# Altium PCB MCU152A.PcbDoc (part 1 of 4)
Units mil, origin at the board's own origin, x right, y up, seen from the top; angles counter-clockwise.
Board outline 2307.9 x 3007.9 mil, 4 copper layers (Top Signal, GND, PWR, Bottom Signal), stack 61.6 mil thick; 198 components, 136 nets, 740 pads, 401 vias.
Unrouted connection lines stored in the file: 147.
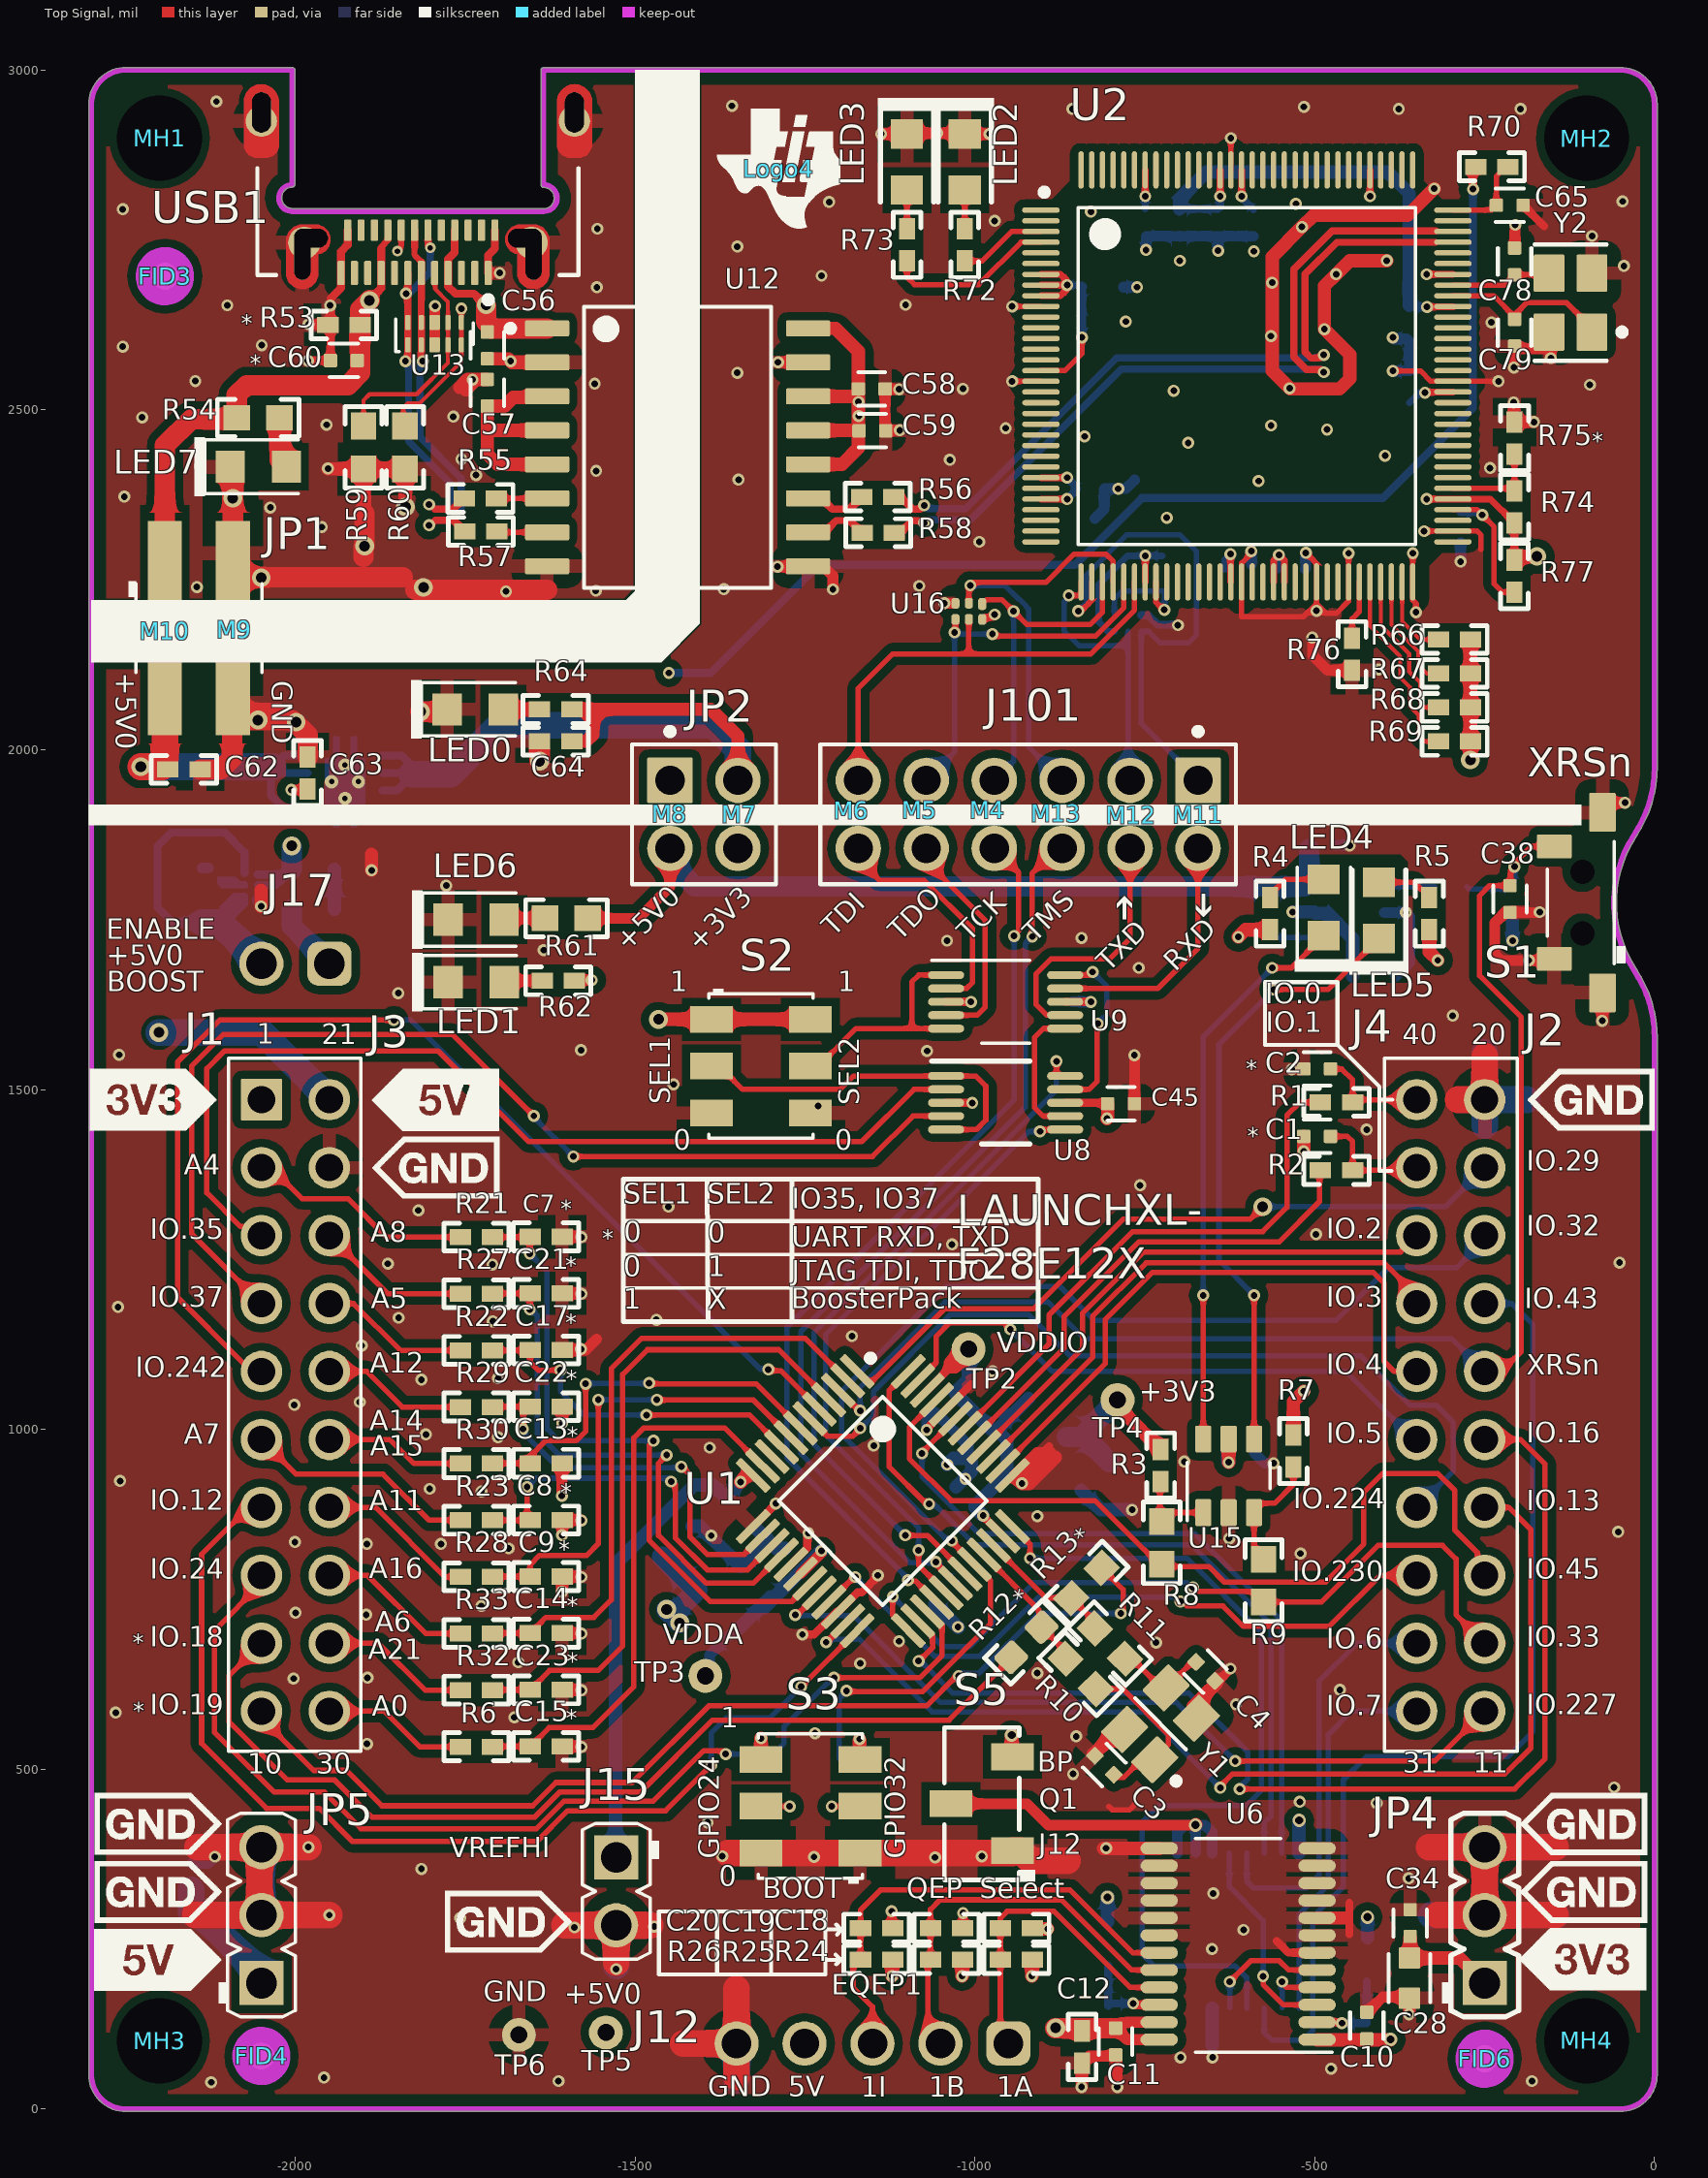
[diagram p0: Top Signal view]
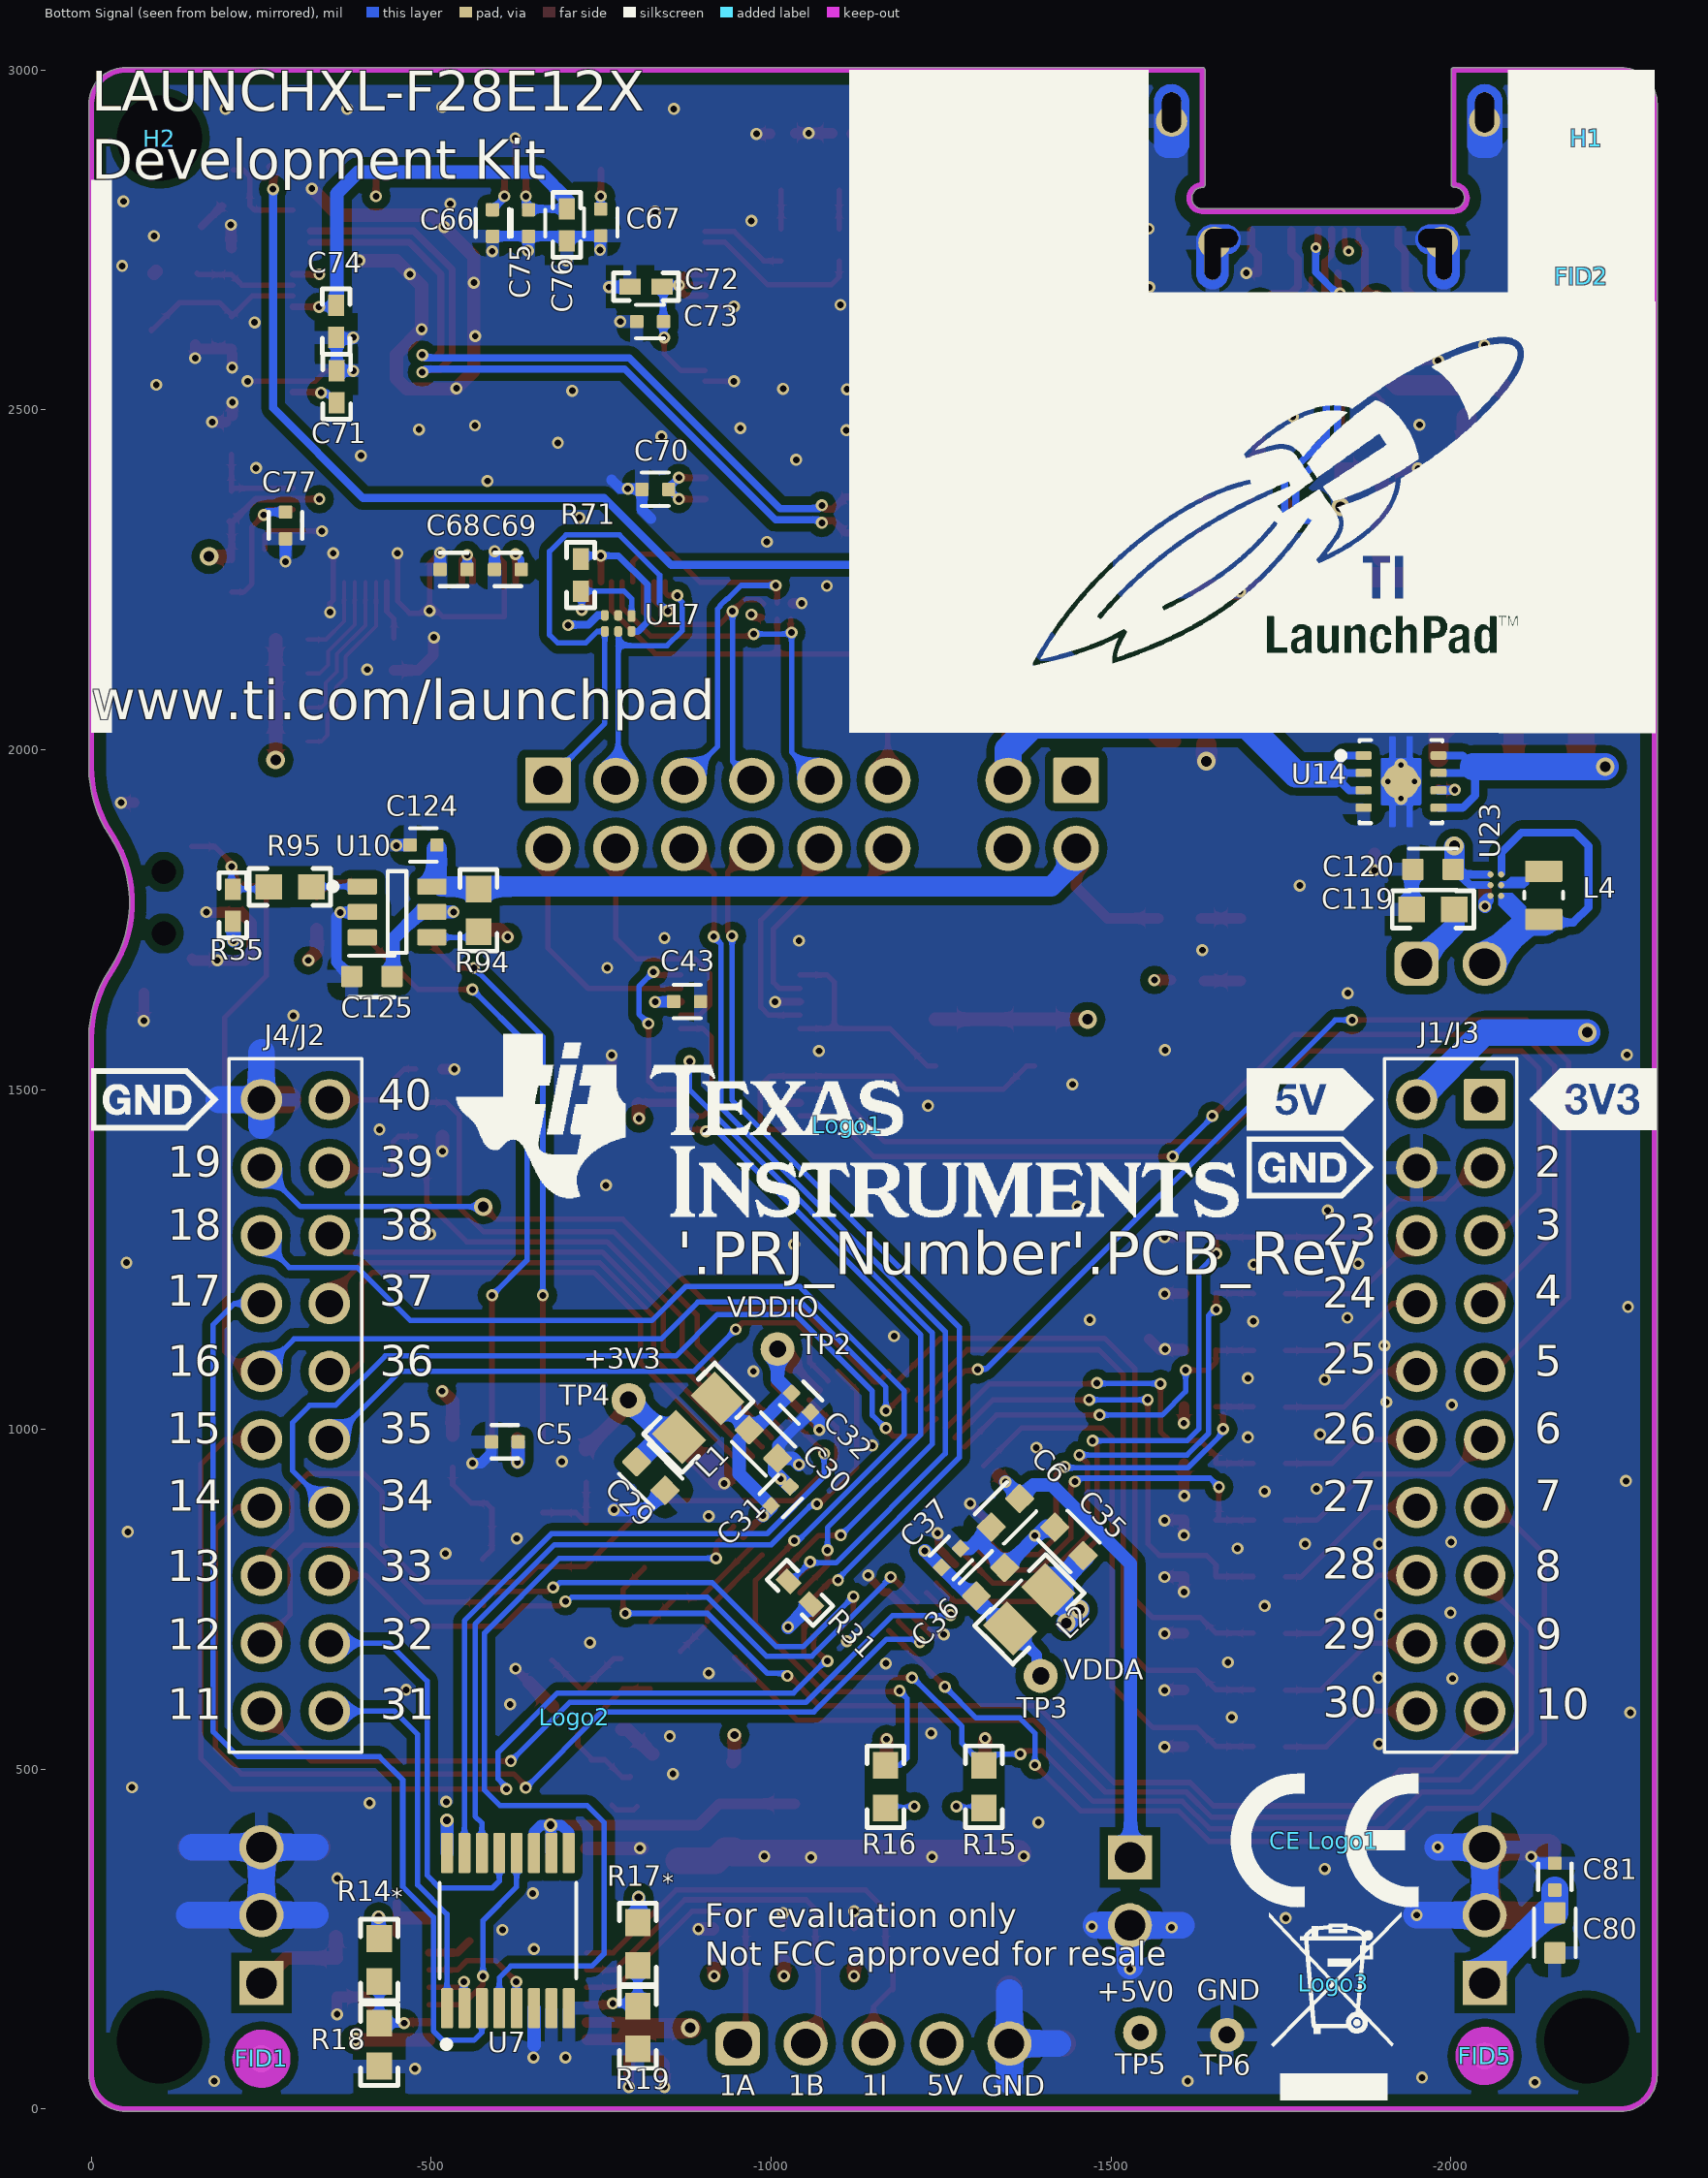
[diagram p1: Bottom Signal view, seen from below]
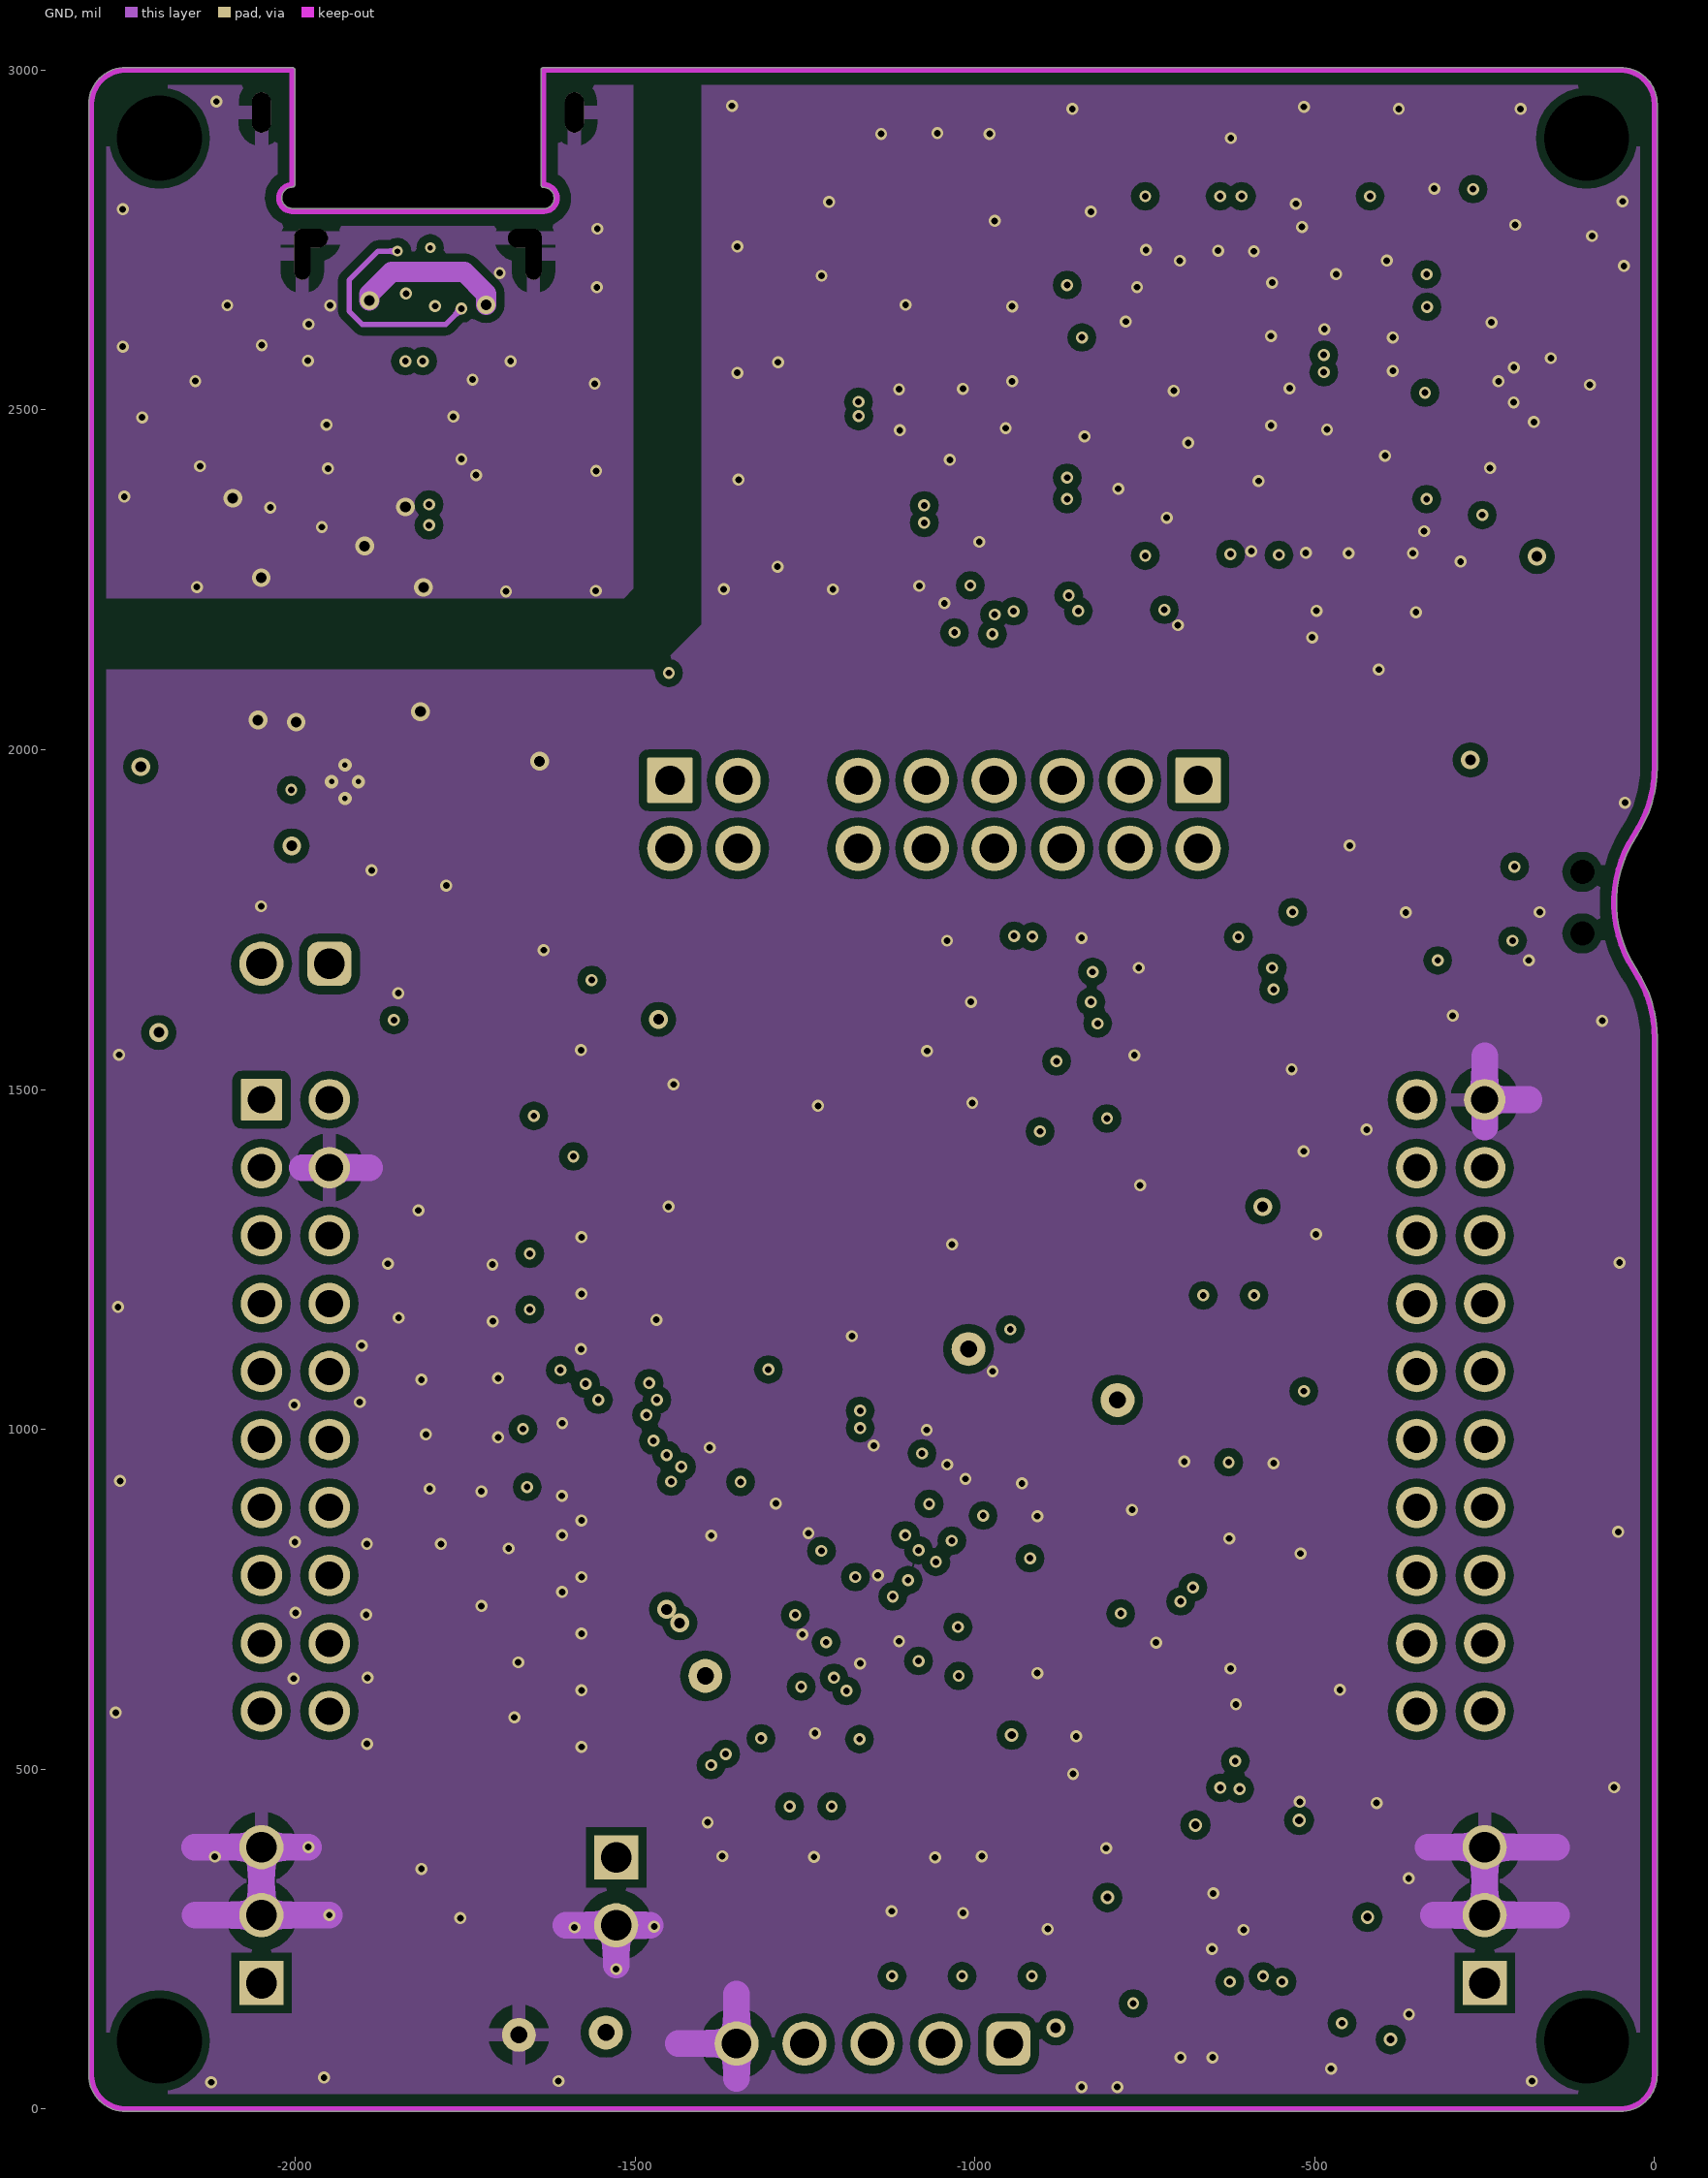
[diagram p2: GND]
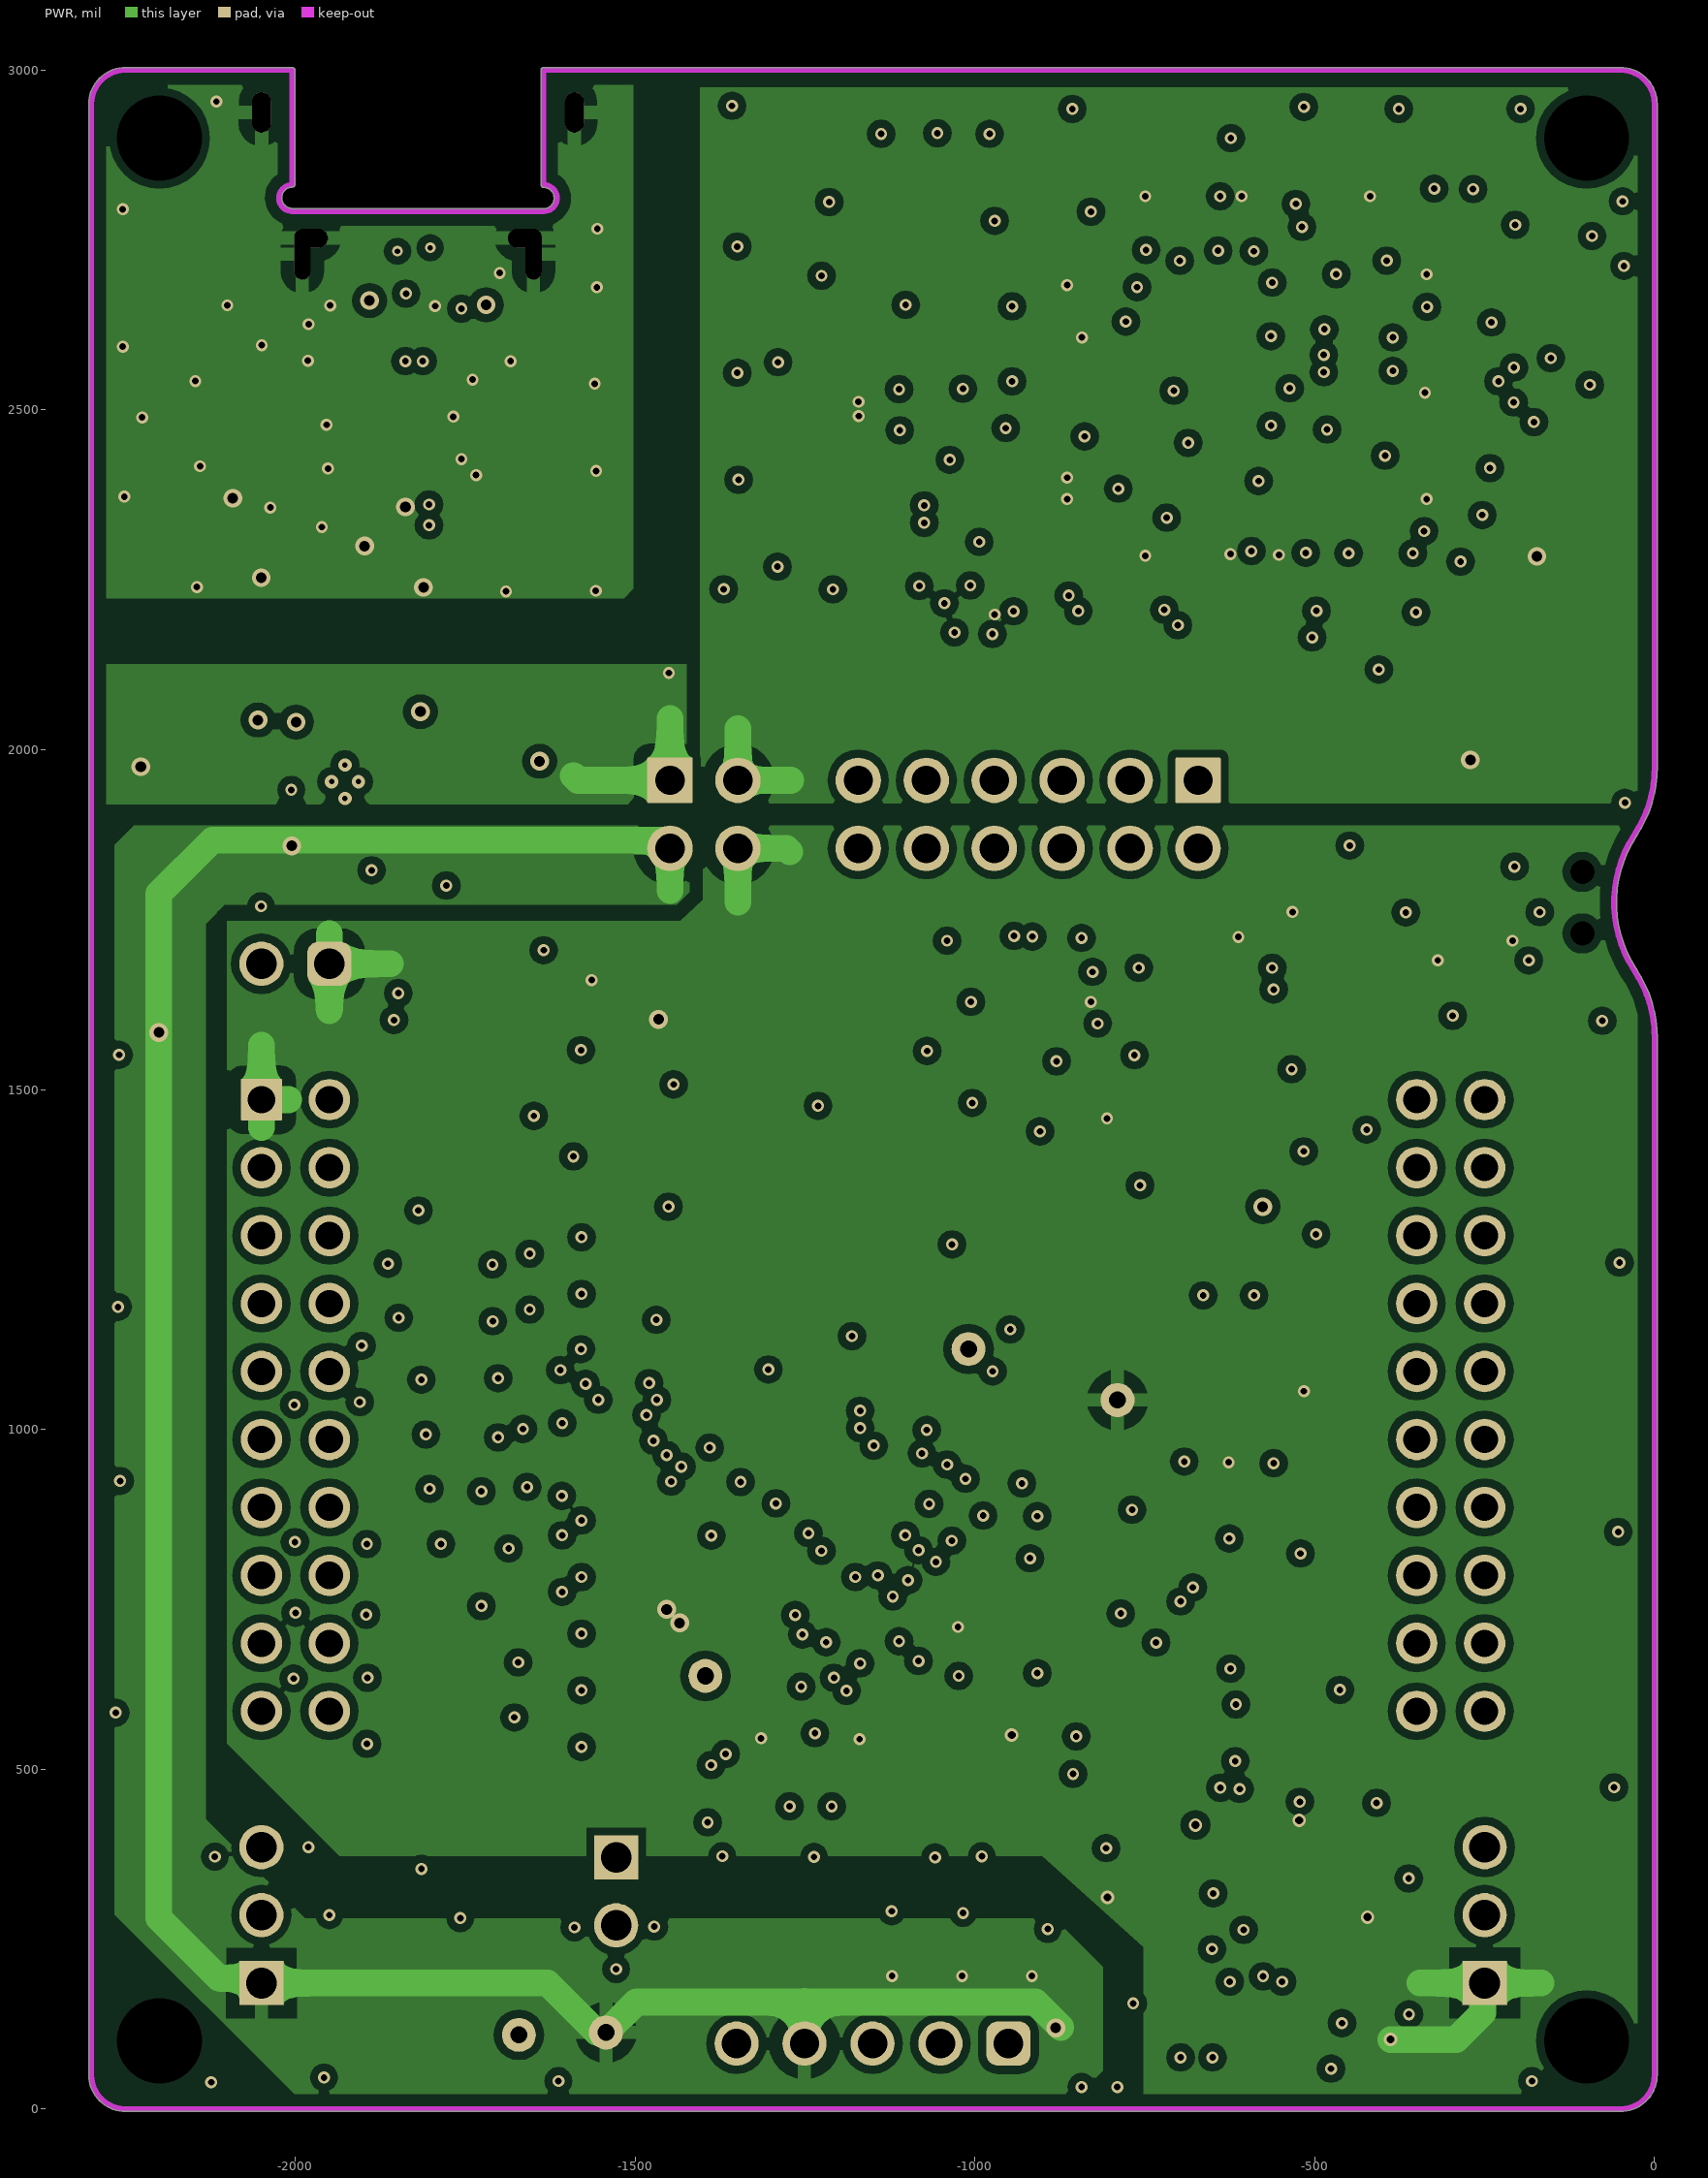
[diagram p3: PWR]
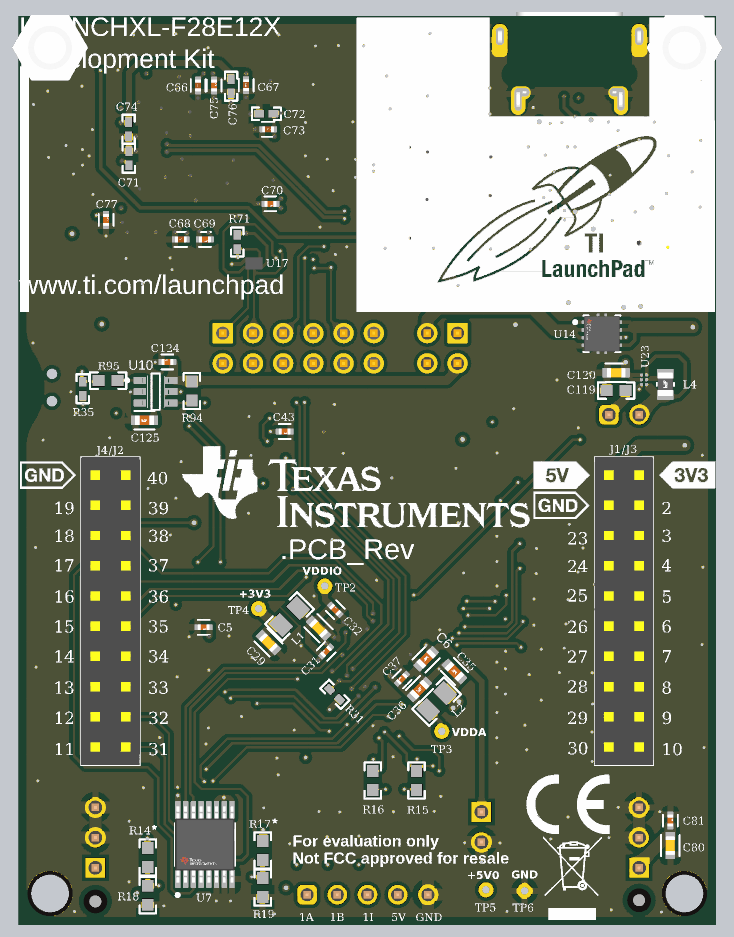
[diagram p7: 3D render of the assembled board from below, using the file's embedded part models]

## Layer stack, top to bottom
Top Solder: solder mask 0.4, Solder Resist, Dk 3.5
Top Signal: signal copper 1.4
Dielectric 1: prepreg 8, FR-4, Dk 4.2
GND: signal copper 1.4
Dielectric 2: core 40, FR-4, Dk 4.2
PWR: signal copper 1.4
Dielectric 3: prepreg 8, FR-4, Dk 4.2
Bottom Signal: signal copper 1.4
Bottom Solder: solder mask 0.4, Solder Resist, Dk 3.5

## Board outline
-2303.95,49.97 cw(c-2300,50) -2303.95,50 -2303.95,2950 cw(c-2250,2950) -2250,3003.95 -2004.72,3003.95 cw(c-2004.72,3000) -2000.77,3000 -2000.77,2832 cw(c-2004.72,2832) -2004.65,2828.05 ccw(c-2004.37,2812.32) -2005.38,2796.62 cw(c-2005.64,2792.67) -2003.63,2796.08 -1634.65,2796.08 cw(c-1634.65,2792.13) -1634.38,2796.07 cw(c-1633.73,2792.17) -1633.99,2796.12 ccw(c-1635,2811.82) -1619.27,2811.82 ccw(c-1635,2811.82) -1634.72,2827.55 cw(c-1634.65,2831.5) -1638.6,2831.5 -1638.6,3000 cw(c-1634.65,3000) -1634.62,3003.95 -50,3003.95 cw(c-50,2950) 3.95,2950 3.95,1975 cw(c-181.67,1975) -26.7,1872.82 ccw(c121.67,1775) -26.7,1677.18 cw(c-181.67,1575) 3.95,1575 3.95,50.03 cw(c0,50) 3.95,50 cw(c-50,50) -50,-3.95 -2250,-3.95 cw(c-2250,50)

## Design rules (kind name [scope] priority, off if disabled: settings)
AcuteAngle [All] p1: minimum=4.50000000000000E+0001 checktracksonly=FALSE
AssemblyTestPointUsage [All] p1: valid=2
BoardOutlineClearance BoardOutlineClearance_MountingHoles [OnCopper and InComponentClass('Mounting Holes')] p1: gap=40 ignorepadtopadclearanceinfootprint=FALSE
BoardOutlineClearance BoardOutlineClearance_Poly [OnCopper and IsPoly] p2: gap=25 ignorepadtopadclearanceinfootprint=FALSE
BoardOutlineClearance BoardOutlineClearance_USB101 [InComponent('USB1')] p3: gap=0 ignorepadtopadclearanceinfootprint=FALSE
BoardOutlineClearance [OnCopper and Not InComponentClass('Logo') and not InComponentClass('FiducialMark') and not InRegion(1000,500,4000,800) and not InPoly] p4: gap=10 ignorepadtopadclearanceinfootprint=FALSE
Clearance USB101 [InComponent('USB1') vs OnLayer('Keep-Out Layer')] p1: gap=7.87 ignorepadtopadclearanceinfootprint=FALSE
Clearance Clearance_1 [inpolygon vs inpolygon] p2: gap=19.68 ignorepadtopadclearanceinfootprint=FALSE
Clearance ISVIA [ISVIA vs ISVIA] p3: gap=7.87 ignorepadtopadclearanceinfootprint=FALSE
Clearance Clearance_FiducialMark [InComponentClass('FiducialMark') vs InComponentClass('FiducialMark')] p4: gap=0 ignorepadtopadclearanceinfootprint=FALSE
Clearance Clearance_Boardedge [All vs IsKeepOut] p5: gap=11.81 ignorepadtopadclearanceinfootprint=FALSE
Clearance INPOLYGON [InPolygon] p6: gap=11.81 ignorepadtopadclearanceinfootprint=FALSE
Clearance [All] p7: gap=5.91 ignorepadtopadclearanceinfootprint=FALSE
ComponentClearance "ComponentClearance_overlay to overlay" [OnBottomSilkscreen vs OnTopSilkscreen] p1: gap=0 collisioncheckmode=3 verticalgap=0 showdistances=FALSE
ComponentClearance ComponentClearance_MountingHoles_FiducialMarks [InComponentClass('Mounting Holes') vs InComponentClass('FiducialMark')] p2: gap=50 collisioncheckmode=3 verticalgap=10 showdistances=FALSE
ComponentClearance ComponentClearance_Shunt [InComponentClass('Header') vs InComponentClass('Shunt')] p3: gap=0 collisioncheckmode=3 verticalgap=0 showdistances=FALSE
ComponentClearance ComponentClearance_Logo [InComponentClass('Logo')] p4: gap=0 collisioncheckmode=3 verticalgap=0 showdistances=FALSE
ComponentClearance ComponentClearance_Logo_1 [InComponentClass('Logo') vs InComponentClass('Logo')] p5: gap=0 collisioncheckmode=3 verticalgap=0 showdistances=FALSE
ComponentClearance ComponentClearance_ScrewToNut [(HasFootprint('NY PMS 440 0025 PH')) vs (HasFootprint('Keystone_1902C'))] p6: gap=3.94 collisioncheckmode=3 verticalgap=3.94 showdistances=FALSE
ComponentClearance ComponentClearance_MountingHoles [InComponentClass('Mounting Holes')] p7 off: gap=250 collisioncheckmode=3 verticalgap=100000 showdistances=FALSE
ComponentClearance ComponentClearance_SmallPassives [HasFootprint('0201*') or HasFootprint('0402*') or HasFootprint('0508') or HasFootprint('0603*') or HasFootprint('0612') or HasFootprint('0805*') or HasFootprint('0815*') or HasFootprint('0830*') or HasFootprint('1206*') or HasFootprint('1210*') or HasFootprint('1808*') or HasFootprint('1812*') or HasFootprint('1825*') or HasFootprint('2010*') or HasFootprint('2220*') or HasFootprint('2225*') or HasFootprint('2512*') or HasFootprint('2728*') or HasFootprint('3518*') vs HasFootprint('0201*') or HasFootprint('0402*') or HasFootprint('0508') or HasFootprint('0603*') or HasFootprint('0612') or HasFootprint('0805*') or HasFootprint('0815*') or HasFootprint('0830*') or HasFootprint('1206*') or HasFootprint('1210*') or HasFootprint('1808*') or HasFootprint('1812*') or HasFootprint('1825*') or HasFootprint('2010*') or HasFootprint('2220*') or HasFootprint('2225*') or HasFootprint('2512*') or HasFootprint('2728*') or HasFootprint('3518*')] p8 off: gap=10 collisioncheckmode=3 verticalgap=0 showdistances=FALSE
ComponentClearance ComponentClearance_THtoSMT [IsThruComponent vs IsSMTComponent] p9 off: gap=10 collisioncheckmode=3 verticalgap=10 showdistances=FALSE
ComponentClearance ComponentClearance_THtoTH [IsThruComponent vs IsThruComponent] p10 off: gap=20 collisioncheckmode=3 verticalgap=30 showdistances=FALSE
DiffPairsRouting [All] p1: maxlimit=100 minlimit=5 mostfreqgap=5.91 toplayer_minwidth=5.91 toplayer_maxwidth=15 toplayer_prefwidth=10.63 midlayer1_minwidth=5.91 midlayer1_maxwidth=15 midlayer1_prefwidth=10.63 midlayer2_minwidth=5.91 midlayer2_maxwidth=15 midlayer2_prefwidth=10.63 bottomlayer_minwidth=5.91 bottomlayer_maxwidth=15 bottomlayer_prefwidth=10.63 substack1={34FF3085-46C3-4105-AC2F-B489268A2D4A} toplayer_{34ff3085-46c3-4105-ac2f-b489268a2d4a}_minwidth=15 toplayer_{34ff3085-46c3-4105-ac2f-b489268a2d4a}_maxwidth=15 toplayer_{34ff3085-46c3-4105-ac2f-b489268a2d4a}_prefwidth=15 midlayer1_{34ff3085-46c3-4105-ac2f-b489268a2d4a}_minwidth=15 midlayer1_{34ff3085-46c3-4105-ac2f-b489268a2d4a}_maxwidth=15 midlayer1_{34ff3085-46c3-4105-ac2f-b489268a2d4a}_prefwidth=15 midlayer2_{34ff3085-46c3-4105-ac2f-b489268a2d4a}_minwidth=15 midlayer2_{34ff3085-46c3-4105-ac2f-b489268a2d4a}_maxwidth=15 midlayer2_{34ff3085-46c3-4105-ac2f-b489268a2d4a}_prefwidth=15 bottomlayer_{34ff3085-46c3-4105-ac2f-b489268a2d4a}_minwidth=15 bottomlayer_{34ff3085-46c3-4105-ac2f-b489268a2d4a}_maxwidth=15 bottomlayer_{34ff3085-46c3-4105-ac2f-b489268a2d4a}_prefwidth=15 substack2={3F2E126A-DFD7-4CD9-AFD3-A2AFD08F7359} toplayer_{3f2e126a-dfd7-4cd9-afd3-a2afd08f7359}_minwidth=15 toplayer_{3f2e126a-dfd7-4cd9-afd3-a2afd08f7359}_maxwidth=15 toplayer_{3f2e126a-dfd7-4cd9-afd3-a2afd08f7359}_prefwidth=15 midlayer1_{3f2e126a-dfd7-4cd9-afd3-a2afd08f7359}_minwidth=15 midlayer1_{3f2e126a-dfd7-4cd9-afd3-a2afd08f7359}_maxwidth=15 midlayer1_{3f2e126a-dfd7-4cd9-afd3-a2afd08f7359}_prefwidth=15 midlayer2_{3f2e126a-dfd7-4cd9-afd3-a2afd08f7359}_minwidth=15 midlayer2_{3f2e126a-dfd7-4cd9-afd3-a2afd08f7359}_maxwidth=15 midlayer2_{3f2e126a-dfd7-4cd9-afd3-a2afd08f7359}_prefwidth=15 bottomlayer_{3f2e126a-dfd7-4cd9-afd3-a2afd08f7359}_minwidth=15 bottomlayer_{3f2e126a-dfd7-4cd9-afd3-a2afd08f7359}_maxwidth=15 bottomlayer_{3f2e126a-dfd7-4cd9-afd3-a2afd08f7359}_prefwidth=15 maxuncoupledlength=1000
FabricationTestPointUsage TestPointUsage [All] p1: valid=2 allowmultiple=FALSE
FabricationTestpoint Testpoint [All] p1: side=3 testpointundercomponent=TRUE minsize=40 maxsize=100 preferedsize=60 minholesize=0 maxholesize=40 preferedholesize=32 testpointgrid=1 allowsidetop=TRUE allowsidebottom=TRUE usegrid=TRUE gridtolerance=0.01
FanoutControl Fanout_LCC [IsLCC] p1: bgadir=Out bgaviamode=Centered fanoutstyle=Auto fanoutdirection=Alternating viagrid=1 // Fanout_LCC (Default Rule)
FanoutControl Fanout_BGA [IsBGA] p2: bgadir=Out bgaviamode=Centered fanoutstyle=Auto fanoutdirection=Alternating viagrid=1 // Fanout_BGA (Default Rule)
FanoutControl Fanout_Default [All] p4: bgadir=Out bgaviamode=Centered fanoutstyle=Auto fanoutdirection=Alternating viagrid=1 // Fanout_Default (Default Rule)
FanoutControl Fanout_Small [(CompPinCount < 5)] p5: bgadir=Out bgaviamode=Centered fanoutstyle=Auto fanoutdirection=OutThenIn viagrid=1 // Fanout_Small (Default Rule)
HoleSize [All] p1: absolutevalues=TRUE maxlimit=251 minlimit=7.87 maxpercent=80.000 minpercent=20.000
HoleToHoleClearance HoleToHoleClearance_Standoff [InComponent('H1') or InComponent('H2') vs InComponent('MH1') or InComponent('MH2')] p1: gap=0 allowstackedmicrovias=TRUE
HoleToHoleClearance HoleToHoleClearance_USB1 [InComponent('USB1') vs InComponent('USB1')] p2: gap=0 allowstackedmicrovias=TRUE
HoleToHoleClearance [All] p3: gap=9.84 allowstackedmicrovias=TRUE
MatchedLengths FSIRX [InNetClass('FSIRX')] p1: tolerance=25 checknetsindiffpair=FALSE checkdiffpairvsdiffpair=TRUE checkxsignals=TRUE checkothers=TRUE
MatchedLengths FSITX [InNetClass('FSITX')] p2: tolerance=25 checknetsindiffpair=FALSE checkdiffpairvsdiffpair=TRUE checkxsignals=TRUE checkothers=TRUE
MinimumAnnularRing MinimumAnnularRing_ThermalPadVias [IsVia and InAnyComponent] p1: minimumring=3.94
MinimumAnnularRing [All] p2: minimumring=3.94
MinimumSolderMaskSliver MinimumSolderMaskSliver_Logo [InComponentClass('Logo') vs InComponentClass('Logo')] p1: minsoldermaskwidth=0.7
MinimumSolderMaskSliver [All] p2: minsoldermaskwidth=3
PlaneClearance [All] p1: clearance=5
PlaneConnect [All] p1: planeconnectstyle=Relief reliefexpansion=10 reliefentries=4 reliefconductorwidth=25 reliefairgap=10
PolygonConnect PolygonConnect_via [isvia or InComponent('TP2')] p1: connectstyle=Direct reliefconductorwidth=10 reliefentries=4 polygonreliefangle="90 Angle" airgapwidth=5
PolygonConnect [All] p2: connectstyle=Relief reliefconductorwidth=20 reliefentries=4 polygonreliefangle="90 Angle" airgapwidth=19.68
RoutingVias ThermalPadVias [IsVia and InAnyComponent] p1: holewidth=7.87 width=19.68 viastyle="Through Hole" minholewidth=7.87 minwidth=19.68 maxholewidth=12.99 maxwidth=23.62
RoutingVias [All] p2: holewidth=9.84 width=17.72 viastyle="Through Hole" minholewidth=7.87 minwidth=15.75 maxholewidth=40 maxwidth=65
ShortCircuit ShortCircuit_Standoff [InComponent('H1') or InComponent('H2') vs InComponent('MH1') or InComponent('MH2')] p1: allowed=TRUE
ShortCircuit [All] p2: allowed=FALSE
SilkToBoardRegionClearance [Not ((IsComment or IsDesignator) And (Hide <> 'False')) and not InRegion(1000,500,4000,800)] p1:
SilkToSilkClearance SilkToSilkClearance_Pb-FreeLogo [(HasFootprint('Pb-Free_Overlay_Medium') OR HasFootprint('Pb-Free_Overlay_Small')) vs (HasFootprint('Pb-Free_Overlay_Medium') OR HasFootprint('Pb-Free_Overlay_Small'))] p1: silktosilkclearance=0
SilkToSilkClearance [All] p2: silktosilkclearance=0
SilkToSolderMaskClearance SilkToComponentPadClearance [(IsPad or IsFill or IsRegion) and InAnycomponent] p1: minsilkscreentomaskgap=0 clearancetoexposedcopper=TRUE
SilkToSolderMaskClearance "Silk to Solder Mask Opening" [All] p2: minsilkscreentomaskgap=0 clearancetoexposedcopper=TRUE
SolderMaskExpansion [All] p1: expansion=2 istentingtop=FALSE
Width Analog [InNetClass('Analog')] p1: maxlimit=25 minlimit=8 preferedwidth=8 substack1={34FF3085-46C3-4105-AC2F-B489268A2D4A} substack2={3F2E126A-DFD7-4CD9-AFD3-A2AFD08F7359}
Width [All] p2: maxlimit=100 minlimit=5 preferedwidth=5 substack1={34FF3085-46C3-4105-AC2F-B489268A2D4A} substack2={3F2E126A-DFD7-4CD9-AFD3-A2AFD08F7359} checkconnectedcopper=TRUE
12 further rules are at their usual default settings.

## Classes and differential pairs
component class MCU152A_ADC: C6 C7 C8 C9 C13 C14 C15 C17 C21 C22 C23 J15 R6 R21 R22 R23 R27 R28 R29 R30 R32 R33
component class MCU152A_USB_and_Power: C28 C34 C56 C57 C58 C59 C60 C62 C63 C64 C80 C81 C119 C120 C124 C125 J17 JP1 JP2 JP4 JP5 JP10 L4 LED0 LED1 LED6 LED7 M4 M5 M6 M7 R53 R54 R55 R56 R57 R58 R59 R60 R61 R62 R64 R94 R95 R103 R105 TP2 TP3 TP4 TP5 TP6 U10 U12 U13 U14 U23 USB1
component class MCU152A_XDS110_MCU: C65 C66 C67 C68 C69 C70 C71 C72 C73 C74 C75 C76 C77 C78 C79 J101 LED2 LED3 M8 M9 M10 M11 M12 M13 R66 R67 R68 R69 R70 R71 R72 R73 R74 R75 R76 R77 R? U2 U16 U17 Y2
component class MCU152A_F28E12X_Device: C29 C30 C31 C32 C35 C36 C37 C38 L1 L2 R31 R35 S1 U1
component class MCU152A_Connectors: C1 C2 C18 C19 C20 J1/J3 J4/J2 J12 R1 R2 R24 R25 R26
component class MCU152A_AltRouting_Misc: C3 C4 C5 C10 C11 C12 C43 C45 LED4 LED5 R3 R4 R5 R7 R8 R9 R10 R11 R12 R13 R14 R15 R16 R17 R18 R19 S2 S3 S5 U6 U7 U8 U9 U15 Y1
component class Header: J12 J15 J17 JP1 JP4 JP5 JP10
component class AssemblyNote: ZZ1 ZZ2 ZZ3
component class FiducialMark: FID1 FID2 FID3 FID4 FID5 FID6
component class MCU152A_Hardware: "CE Logo1" FID1 FID2 FID3 FID4 FID5 FID6 H1 H2 Logo1 Logo2 Logo3 Logo4 MH1 MH2 MH3 MH4 ZZ1 ZZ2 ZZ3
component class Logo: Logo1 Logo4
component class Shunt: M4 M5 M6 M7 M8 M9 M10 M11 M12 M13
differential pair XDS_D: +XDS_D_P -XDS_D_N
differential pair USB_D: +USB_D_P -USB_D_N

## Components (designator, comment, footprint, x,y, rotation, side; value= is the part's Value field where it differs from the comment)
C1 "885012205018" FP-885012205018_0402-MFG -496.52,1431 r0 top value=100nF
C2 "885012205018" FP-885012205018_0402-MFG -496.52,1530.25 r0 top value=100nF
C3 "885392005127" FP-885392005127_0402-MFG -809.63,505.63 r135 top value=12pF
C4 "885392005127" FP-885392005127_0402-MFG -660.75,643.57 r315 top value=12pF
C5 "885012205018" FP-885012205018_0402-MFG -608.26,981.45 r180 bottom value=100nF
C6 "885012106011" FP-885012106011_0603-MFG -1344.89,877 r315 bottom value=2.2µF
C7 "GRM1555C1H331JA01D" 0402 -1631,1283.21 r0 top value=330pF
C8 "GRM1555C1H331JA01D" 0402 -1631,866.54 r0 top value=330pF
C9 "GRM1555C1H331JA01D" 0402 -1631,783.21 r0 top value=330pF
C10 "885012205018" FP-885012205018_0402-MFG -423.5,122.36 r90 top value=100nF
C11 "885012205018" FP-885012205018_0402-MFG -793,99 r90 top value=100nF
C12 "885012205061" 0402 -842.19,91 r270 top value=1000pF
C13 "GRM1555C1H331JA01D" 0402 -1631,949.88 r0 top value=330pF
C14 "GRM1555C1H331JA01D" 0402 -1631,699.88 r0 top value=330pF
C15 "GRM1555C1H331JA01D" 0402 -1631,533.21 r0 top value=330pF
C17 "GRM1555C1H331JA01D" 0402 -1631,1116.54 r0 top value=330pF
C18 "885012205061" 0402 -939,266 r0 top value=1000pF
C19 "885012205061" 0402 -1041.73,266 r0 top value=1000pF
C20 "885012205061" 0402 -1144.73,266 r0 top value=1000pF
C21 "GRM1555C1H331JA01D" 0402 -1631,1199.88 r0 top value=330pF
C22 "GRM1555C1H331JA01D" 0402 -1631,1033.21 r0 top value=330pF
C23 "GRM1555C1H331JA01D" 0402 -1631,616.54 r0 top value=330pF
C28 "885012106031" FP-885012106031_0603-MFG -360.65,192.28 r270 top value=10µF
C29 "885012106031" FP-885012106031_0603-MFG -823,931 r225 bottom value=10µF
C30 "885012106031" FP-885012106031_0603-MFG -988.73,978 r225 bottom value=10µF
C31 "885012205018" FP-885012205018_0402-MFG -1014,901.34 r315 bottom value=100nF
C32 "885012205018" FP-885012205018_0402-MFG -1044,1039 r45 bottom value=100nF
C34 "885012205018" FP-885012205018_0402-MFG -359.68,273.23 r90 top value=100nF
C35 "885012106011" FP-885012106011_0603-MFG -1438.32,835 r45 bottom value=2.2µF
C36 "885012106011" FP-885012106011_0603-MFG -1322.91,775.48 r135 bottom value=2.2µF
C37 "885012205018" FP-885012205018_0402-MFG -1264.89,810.66 r315 bottom value=100nF
C38 "885012205018" FP-885012205018_0402-MFG -212.72,1780.29 r90 top value=100nF
C43 "885012205018" FP-885012205018_0402-MFG -876.5,1629.38 r180 bottom value=100nF
C45 "885012205018" FP-885012205018_0402-MFG -785,1479 r0 top value=100nF
C56 "885012205018" FP-885012205018_0402-MFG -1717.56,2595 r90 top value=100nF
C57 "885012205018" FP-885012205018_0402-MFG -1717.56,2525.32 r270 top value=100nF
C58 "885012205018" FP-885012205018_0402-MFG -1152,2531 r180 top value=100nF
C59 "885012205018" FP-885012205018_0402-MFG -1150.98,2469.37 r180 top value=100nF
C60 "885012205064" FP-885012205064_0402-MFG -1928.7,2572.8 r0 top value=3.3nF
C62 "885012105012" 0402 -2164,1971 r0 top value=1uF
C63 "885012205061" 0402 -1982.12,1965.8 r90 top value=1000pF
C64 "C1005X5R1A475K050BC" 0402_065 -1616.96,2012.39 r180 top value=4.7uF
C65 "885012205050" FP-885012205050_0402-MFG -213.11,2801.22 r180 top value=10nF
C66 "885012205050" FP-885012205050_0402-MFG -590,2775 r90 bottom value=10nF
C67 "885012205050" FP-885012205050_0402-MFG -749.21,2775.91 r90 bottom value=10nF
C68 "885012205050" FP-885012205050_0402-MFG -532.72,2265.28 r180 bottom value=10nF
C69 "885012205018" FP-885012205018_0402-MFG -612.64,2265.28 r180 bottom value=100nF
C70 "885012205018" FP-885012205018_0402-MFG -829.57,2383.11 r180 bottom value=100nF
C71 "885012105012" 0402 -360.79,2534.13 r90 bottom value=1uF
C72 "885012105012" 0402 -816.02,2681.42 r0 bottom value=1uF
C73 "885012205050" FP-885012205050_0402-MFG -822,2630 r180 bottom value=10nF
C74 "885012105012" 0402 -359.96,2630.28 r270 bottom value=1uF
C75 "885012205018" FP-885012205018_0402-MFG -643.15,2774.92 r90 bottom value=100nF
C76 "885012105012" 0402 -699.17,2772.4 r270 bottom value=1uF
C77 "885012205018" FP-885012205018_0402-MFG -285.47,2330.04 r90 bottom value=100nF
C78 "885392005127" FP-885392005127_0402-MFG -205.98,2718.62 r90 top value=12pF
C79 "885392005127" FP-885392005127_0402-MFG -205.98,2613.62 r270 top value=12pF
C80 "885012106031" FP-885012106031_0603-MFG -2153.25,258.94 r270 bottom value=10µF
C81 "885012205018" FP-885012205018_0402-MFG -2153.25,341.56 r90 bottom value=100nF
C119 "885012106018" 0603#1 -1974,1765 r0 bottom value=2.2uF
C120 "885012106031" FP-885012106031_0603-MFG -1974,1824 r0 bottom value=10µF
C124 "885012205018" FP-885012205018_0402-MFG -488.45,1859.72 r0 bottom value=100nF
C125 "885012206040" FP-885012206040_0603-MFG -412.55,1666.45 r180 bottom value=10nF
"CE Logo1" "CE Mark" CE_Mark_5mm -1814.5,395.06 r180 bottom
FID1 "Fiducial" Fiducial10-20 -250,73.69 r180 bottom
FID2 "Fiducial" Fiducial10-20 -2192.13,2696.88 r180 bottom
FID3 "Fiducial" Fiducial10-20 -2192.13,2696.88 r0 top
FID4 "Fiducial" Fiducial10-20 -2050,77.66 r0 top
FID5 "Fiducial" Fiducial10-20 -2050,77.66 r180 bottom
FID6 "Fiducial" Fiducial10-20 -250,73.69 r0 top
H1 "MAE-10" KY_MAE-10 -2200,2900 r180 bottom
H2 "MAE-10" KY_MAE-10 -100,2900 r180 bottom
J1/J3 "SSQ-110-03-T-D" BOOSTERPACK_40PIN_J1J3 -2000,1035 r180 bottom locked
J4/J2 "SSQ-110-03-T-D" BoosterPack_40pin_J2J4 -300,1035 r180 bottom locked
J12 "61300511121" Wurth_61300511121 -1150.8,95.98 r180 top
J15 "61300211121" WURTH_61300211121#1 -1528,320 r270 top
J17 "61300211121" WURTH_61300211121#2 -2000,1685 r180 top
J101 "61301221121" FP-61301221121_HDR12-MFG -921.67,1905 r180 top
JP1 "TSM-102-01-L-DV" Samtec_TSM-102-01-x-DV -2141.97,2179 r270 top
JP2 "61300421121" FP-61300421121_HDR4-MFG -1398.85,1905 r0 top
JP4 "61300311121" WURTH_61300311121 -250,285 r90 top
JP5 "61300311121" WURTH_61300311121 -2050,285 r90 top
L1 "742792022" 0805_HV -893,1016.97 r135 bottom value="220 ohm"
L2 "742792063" 0805_HV -1379.89,735 r315 bottom value="60 ohm"
L4 "74479773210" FP-74479773210_0805-MFG -2137,1785.73 r90 bottom value=1uH
LED0 "150080SS75000" WL-SMCW_RED_0805 -1735.48,2059.39 r0 top value=Red
LED1 "150080SS75000" WL-SMCW_RED_0805 -1734.13,1658.04 r0 top value=Red
LED2 "150080BS75000" WL-SMCW_Blue_0805 -1015,2865 r270 top value=Blue
LED3 "150080BS75000" WL-SMCW_Blue_0805 -1100,2865 r270 top value=Blue
LED4 "150080SS75000" WL-SMCW_RED_0805 -486.7,1768.01 r90 top value=Red
LED5 "150080GS75000" WL-SMCW_Green_0805 -405.69,1763.56 r90 top value=Green
LED6 "150080SS75000" WL-SMCW_RED_0805 -1734.19,1750 r0 top value=Red
LED7 "150080SS75000" WL-SMCW_RED_0805 -2054.49,2416.38 r0 top value=Red
Logo1 "Texas Instruments" TI_Stacked_Overlay_Medium -1112.5,1447.5 r180 bottom locked
Logo2 "FCC disclaimer" FCC_disclaimer -711.18,576.75 r180 bottom locked
Logo3 "WEEE logo" WEEE_Minimum -1828,185 r180 bottom
Logo4 "Texas Instruments" TI_Symbol_Overlay_Small -1289.17,2855 r0 top
M4 "60900213421" Wurth_60900213421 -981.67,1911 r90 top
M5 "60900213421" Wurth_60900213421 -1081.67,1911 r90 top
M6 "60900213421" Wurth_60900213421 -1181.67,1911 r90 top
M7 "60900213421" Wurth_60900213421 -1346.89,1905 r90 top
M8 "60900213421" Wurth_60900213421 -1449.1,1906 r90 top
M9 "60900213421" Wurth_60900213421 -2089.96,2176.85 r90 top
M10 "60900213421" Wurth_60900213421 -2191.89,2175 r90 top
M11 "60900213421" Wurth_60900213421 -671,1904 r90 top
M12 "60900213421" Wurth_60900213421 -769.41,1904.02 r90 top locked
M13 "60900213421" Wurth_60900213421 -880.5,1907 r90 top
MH1 "MTG_NoPads" NPTH125mil -2200,2900 r0 top
MH2 "MTG_NoPads" NPTH125mil -100,2900 r0 top
MH3 "MTG_NoPads" NPTH125mil -2200,100 r0 top
MH4 "MTG_NoPads" NPTH125mil -100,100 r0 top
R1 "RC0402JR-070RL" 0402 -468,1481 r0 top value=0
R2 "RC0402JR-070RL" 0402 -468,1381 r0 top value=0
R3 "CRCW040210M0JNED" 0402 -726.7,946.66 r90 top value=10Meg
R4 "CRCW0402680RJNED" 0402 -565.85,1758.79 r270 top value=680
R5 "CRCW0402680RJNED" 0402 -331.49,1758.79 r270 top value=680
R6 "RC0402JR-070RL" 0402 -1733.63,532.79 r0 top value=0
R7 "CRCW040210M0JNED" 0402 -531.44,967.91 r90 top value=10Meg
R8 "CRCW06030000Z0EA" 0603#1 -725,832.88 r90 top value=0
R9 "CRCW06030000Z0EA" 0603#1 -575.17,777.21 r90 top value=0
R10 "FC0603E50R0BTBST1" 0603#1 -844.37,640.09 r315 top value=50
R11 "CRCW06030000Z0EA" 0603#1 -801.36,684.57 r315 top value=0
R12 "CRCW06030000Z0EA" 0603#2 -924.29,686.55 r45 top value=0
R13 "CRCW06030000Z0EA" 0603#1 -836.06,773.74 r225 top value=0
R14 "CRCW06030000Z0EA" 0603#1 -423.5,219 r90 bottom value=0
R15 "RC0603FR-0710KL" 0603#1 -1313.08,473.93 r270 bottom value=10.0k
R16 "RC0603FR-0710KL" 0603#1 -1168.35,473.93 r90 bottom value=10.0k
R17 "CRCW06032K20JNEA" 0603#1 -804,242.5 r90 bottom value=2.2k
R18 "CRCW06030000Z0EA" 0603#1 -423.5,94.3 r90 bottom value=0
R19 "CRCW06030000Z0EA" 0603#1 -803.83,119.67 r270 bottom value=0
R21 "RC0402JR-070RL" 0402 -1733.63,1282.79 r0 top value=0
R22 "RC0402JR-070RL" 0402 -1733.63,1116.12 r0 top value=0
R23 "RC0402JR-070RL" 0402 -1733.63,866.12 r0 top value=0
R24 "CRCW04021K00FKED" 0402 -939,219.62 r0 top value=1.00k
R25 "CRCW04021K00FKED" 0402 -1041.73,219.62 r0 top value=1.00k
R26 "CRCW04021K00FKED" 0402 -1144.73,219.62 r0 top value=1.00k
R27 "RC0402JR-070RL" 0402 -1733.63,1199.46 r0 top value=0
R28 "RC0402JR-070RL" 0402 -1733.63,782.79 r0 top value=0
R29 "RC0402JR-070RL" 0402 -1733.63,1032.79 r0 top value=0
R30 "RC0402JR-070RL" 0402 -1733.63,949.46 r0 top value=0
R31 "CRCW04022K20JNED" 0402 -1042.41,759.41 r225 bottom value=2.2k
R32 "RC0402JR-070RL" 0402 -1733.63,616.12 r0 top value=0
R33 "RC0402JR-070RL" 0402 -1733.63,699.46 r0 top value=0
R35 "CRCW04022K20JNED" 0402 -208,1771.19 r270 bottom value=2.2k
R53 "CRCW04021M00FKED" 0402 -1928.62,2625 r0 top value=1.00Meg
R54 "RC0603JR-073KL" 0603#1 -2054.8,2488.35 r180 top value=3.0k
R55 "RC0402JR-070RL" 0402 -1727.76,2370 r0 top value=0
R56 "RC0402JR-070RL" 0402 -1143.11,2371.85 r0 top value=0
R57 "RC0402JR-070RL" 0402 -1727.11,2321.44 r0 top value=0
R58 "RC0402JR-070RL" 0402 -1142.4,2319.37 r0 top value=0
R59 "RC0603JR-075K1L" 0603#1 -1899.62,2444.88 r90 top value=5.1k
R60 "RC0603JR-075K1L" 0603#1 -1838.66,2444.88 r90 top value=5.1k
R61 "RC0603JR-073KL" 0603#1 -1601.27,1752 r0 top value=3.0k
R62 "CRCW0402680RJNED" 0402 -1613.25,1660 r0 top value=680
R64 "CRCW0402680RJNED" 0402 -1616.96,2059.39 r0 top value=680
R66 "CRCW04021K00FKED" 0402 -294.24,2162.21 r0 top value=1.00k
R67 "CRCW04021K00FKED" 0402 -294.24,2112.21 r0 top value=1.00k
R68 "CRCW04021K00FKED" 0402 -294.24,2062.21 r0 top value=1.00k
R69 "CRCW04021K00FKED" 0402 -294.24,2012.21 r0 top value=1.00k
R70 "CRCW0402100RJNED" 0402 -239.29,2857.91 r0 top value=100
R71 "CRCW04023K30JNED" 0402 -719.82,2257 r90 bottom value=3.3k
R72 "RC0402FR-07470RL" 0402 -1015,2742.99 r270 top value=470
R73 "RC0402FR-07470RL" 0402 -1100,2742.99 r270 top value=470
R74 "CRCW040210K0JNED" 0402 -205.98,2357.09 r270 top value=10k
R75 "CRCW040210K0JNED" 0402 -205.98,2458.62 r270 top value=10k
R76 "CRCW04024K87FKED" 0402 -445,2140.56 r90 top value=4.87k
R77 "CRCW040251R0JNED" 0402 -206.34,2255.59 r90 top value=51
R94 "RC0603FR-0747KL" 0603#1 -569.55,1763.56 r90 bottom value=47.0k
R95 "ERJ-3GEY0R00V" 0603#1 -292,1798.01 r180 bottom value=0
S1 "1188E-1K2-V-TR" SW_1188E -120,1775 r180 top locked
S2 "CAS-D20TA" SW_CAS-D20TA -1314.85,1534.31 r0 top
S3 "CAS-D20TA" SW_CAS-D20TA -1242.04,445.26 r180 top
S5 "CAS-120TA" SW_CAS-120TA -990,449 r180 top
TP2 "TESTPOINT" TP_50MIL-25MILHOLE -1009.5,1118.03 r0 top
TP3 "TESTPOINT" TP_50MIL-25MILHOLE -1396.67,637 r0 top
TP4 "TESTPOINT" TP_50MIL-25MILHOLE -790.17,1043 r0 top
TP5 "TESTPOINT" TP_50MIL-25MILHOLE -1543,112.22 r0 top
TP6 "TESTPOINT" TP_50MIL-25MILHOLE -1671.11,108.72 r0 top
U1 "F28E120SCTPT" PT0048A-MFG -1135.67,894.43 r315 top locked
U2 "MSP432E401YTPDT" PDT0128A -599.8,2550 r0 top locked
U6 "SN74LVC8T245PW" PW0024A_N -612.75,242.5 r180 top locked
U7 "SN74LV4053APWR" PW0016A-MFG -612.75,262.19 r90 bottom
U8 "TS5A23157DGSR" DGS0010A_N -954.91,1480.5 r0 top
U9 "TS5A23157DGSR" DGS0010A_N -954.91,1629 r0 top
U10 "TPS3808EG33DBVR" DBV0006A-MFG -449.63,1761.32 r180 bottom
U12 "ISOUSB111DW" DW0016B-MFG -1437.56,2445 r0 top
U13 "TPD4E05U06DQAR" DQA0010A -1795.16,2612.28 r90 top
U14 "TPS7A8033DRBR" DRB0008A-MFG -1927,1953 r180 bottom
U15 "SN74LVC2G07DBVR" DBV0006A_N -626.7,931.46 r90 top
U16 "TPD4E004DRYR" DRY0006A -1009,2203.72 r270 top
U17 "TPD4E004DRYR" DRY0006A -775,2186 r270 bottom
U23 "TPS61241YFFR" YFF0006AEAE -2066.5,1800.73 r0 bottom
USB1 "MUP-U22001" FP-MUP-U22001_CONN_USB_8MM94_8MM0-MFG -1819.68,2861.03 r180 top locked
Y1 "830108207209" FP-830108207209_SMT_CRYSTAL_3MM2_2MM5-MFG -727,566.48 r45 top
Y2 "830064296" FP-830064296_SMT4_3MM4_2MM7-MFG -123.62,2657.91 r90 top
ZZ1 "These assemblies are ESD sensitive, ESD precautions shall be observed." AssemblyNote -1843,6967 r0 top
ZZ2 "These assemblies must be clean and free from flux and all contaminants. Use of no clean flux is not acceptable." AssemblyNote -1849,6832 r0 top
ZZ3 "These assemblies must comply with workmanship standards IPC-A-610 Class 2, unless otherwise specified." AssemblyNote -1842,6716 r0 top

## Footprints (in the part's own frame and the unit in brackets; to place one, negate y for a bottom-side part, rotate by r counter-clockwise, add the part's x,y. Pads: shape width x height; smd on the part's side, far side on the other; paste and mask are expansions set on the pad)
0402 [mm] "0402 from SM-752 data"
  rect 0.8x0.6 smd: 1(-0.6,0) 2(0.6,0)
  silkscreen extent -1.22,-0.52 1.22,0.52, body extent -0.55,-0.3 0.55,0.3, height 0.6
0402_065 [mm] "0402"
  rect 0.8x0.6 smd: 1(-0.6,0) 2(0.6,0)
  silkscreen extent -1.22,-0.52 1.22,0.52, body extent -0.55,-0.3 0.55,0.3, height 0.65
0603#1 [mm] "0603 from SM-752 data"
  rect 1x0.95 smd: 1(-0.8,0) 2(0.8,0)
  silkscreen extent -1.52,-0.69 1.52,0.69, body extent -0.87,-0.47 0.87,0.47, height 1
0603#2 [mm] "0603 from SM-752 data"
  rrect30% 1x0.95 smd: 1(-0.8,0) 2(0.8,0)
  silkscreen extent -1.52,-0.69 1.52,0.69, body extent -0.87,-0.47 0.87,0.47, height 1
0805_HV [mil] "0805 with 30mil clearance between pads"
  rect 50x63 smd: 1(-40,0) 2(40,0)
  silkscreen extent -74,-40 74,40, body extent -43,-29 43,29, height 57
AssemblyNote [mil] "Assembly Note"
BOOSTERPACK_40PIN_J1J3 [mm] "Receptacle, 2.54mm, 10x2, TH"
  rrect6% 1.55x1.55 hole 1.02: 1(1.27,11.43)
  round 1.55 hole 1.02: 2(1.27,8.89) 3(1.27,6.35) 4(1.27,3.81) 5(1.27,1.27) 6(1.27,-1.27) 7(1.27,-3.81) 8(1.27,-6.35) 9(1.27,-8.89) 10(1.27,-11.43) 21(-1.27,11.43) 22(-1.27,8.89) 23(-1.27,6.35) 24(-1.27,3.81) 25(-1.27,1.27) 26(-1.27,-1.27) 27(-1.27,-3.81) 28(-1.27,-6.35) 29(-1.27,-8.89) 30(-1.27,-11.43)
  silkscreen extent -7.62,-12.95 7.68,12.95, body extent -2.48,-12.95 2.48,12.95, height 8.51
BoosterPack_40pin_J2J4 [mm] "Receptacle, 2.54mm, 10x2, TH"
  round 1.55 hole 1.02: 11(-1.27,-11.43) 12(-1.27,-8.89) 13(-1.27,-6.35) 14(-1.27,-3.81) 15(-1.27,-1.27) 16(-1.27,1.27) 17(-1.27,3.81) 18(-1.27,6.35) 19(-1.27,8.89) 20(-1.27,11.43) 31(1.27,-11.43) 32(1.27,-8.89) 33(1.27,-6.35) 34(1.27,-3.81) 35(1.27,-1.27) 36(1.27,1.27) 37(1.27,3.81) 38(1.27,6.35) 39(1.27,8.89) 40(1.27,11.43)
  silkscreen extent -7.62,-12.95 2.48,12.95, body extent -2.48,-12.95 2.48,12.95, height 8.51
CE_Mark_5mm [mil] "Minimum text height for CE Mark"
  silkscreen extent -138,-98 138,98
DBV0006A-MFG [mm]
  rrect17% 1.1x0.6 smd paste+0 mask+0: 1(-1.3,0.95) 2(-1.3,0) 3(-1.3,-0.95) 4(1.3,-0.95) 5(1.3,0) 6(1.3,0.95)
  silkscreen extent -2.52,-1.53 0.35,1.53, body extent -1.4,-1.45 1.4,1.45, height 1.45
DBV0006A_N [mm] "SOT23, 6-Leads, Body 2.9x1.6mm, Pitch 0.95mm, Lead Span 2.8mm, IPC Medium Density"
  rrect17% 1x0.6 smd: 1(-1.375,0.95) 2(-1.375,0) 3(-1.375,-0.95) 4(1.375,-0.95) 5(1.375,0) 6(1.375,0.95)
  silkscreen extent -1.67,-1.55 0.5,1.55, body extent -1.42,-1.46 1.42,1.46, height 1.12
DGS0010A_N [mm] "TSSOP, 10-Leads, Body 3x3mm, Pitch 0.5mm, IPC Medium Density"
  oval 1.35x0.3 smd: 1(-2.225,1) 2(-2.225,0.5) 3(-2.225,0) 4(-2.225,-0.5) 5(-2.225,-1) 6(2.225,-1) 7(2.225,-0.5) 8(2.225,0) 9(2.225,0.5) 10(2.225,1)
  silkscreen extent -2.75,-1.55 0.9,1.55, body extent 0,0 0,0, height 0.62
DQA0010A [mm] "SON, 10-Leads, Body 1x2.5mm, Pitch 0.5mm, TI Recommended"
  rrect50% 0.565x0.2 smd: 1(-0.417,1) 2(-0.418,0.5) 4(-0.418,-0.5) 5(-0.418,-1) 6(0.417,-1) 7(0.417,-0.5) 9(0.417,0.5) 10(0.417,1)
  rrect25% 0.565x0.4 smd paste-0.2: 3(-0.418,0) 8(0.417,0)
  rrect28% 0.565x0.36 on Top Paste: 3(-0.418,0) 8(0.417,0)
  silkscreen extent -0.67,-1.45 0.55,1.45, body extent -0.55,-1.3 0.55,1.3, height 0.56
DRB0008A-MFG [mm] "Recommended Land Pattern"
  rrect32% 0.6x0.31 smd paste+0 mask+0: 1(-1.4,0.975) 2(-1.4,0.325) 3(-1.4,-0.325) 4(-1.4,-0.975) 5(1.4,-0.975) 6(1.4,-0.325) 7(1.4,0.325) 8(1.4,0.975)
  round 1.35 smd paste-1000 mask+0: 9(0,0)
  Top Signal region: -0.75,-0.825 -0.743,-0.85 -0.725,-0.868 -0.7,-0.875 -0.7,-0.875 -0.49,-0.875 -0.471,-0.879 -0.455,-0.89 -0.444,-0.906 -0.44,-0.925 -0.44,-0.925 -0.44,-1.65 -0.433,-1.675 -0.415,-1.693 -0.39,-1.7 -0.39,-1.7 -0.26,-1.7 -0.241,-1.696 -0.225,-1.685 -0.214,-1.669 -0.21,-1.65 -0.21,-1.65 -0.21,-0.925 -0.206,-0.906 -0.195,-0.89 -0.179,-0.879 -0.16,-0.875 -0.16,-0.875 0.16,-0.875 0.179,-0.879 0.195,-0.89 0.206,-0.906 0.21,-0.925 0.21,-0.925 0.21,-1.65 0.217,-1.675 0.235,-1.693 0.26,-1.7 0.26,-1.7 0.39,-1.7 0.415,-1.693 0.433,-1.675 0.44,-1.65 0.44,-1.65 0.44,-0.925 0.444,-0.906 0.455,-0.89 0.471,-0.879 0.49,-0.875 0.49,-0.875 0.7,-0.875 0.725,-0.868 0.743,-0.85 0.75,-0.825 0.75,-0.825 0.75,0.825 0.743,0.85 0.725,0.868 0.7,0.875 0.7,0.875 0.49,0.875 0.471,0.879 0.455,0.89 0.444,0.906 0.44,0.925 0.44,0.925 0.44,1.65 0.433,1.675 0.415,1.693 0.39,1.7 0.39,1.7 0.26,1.7 0.235,1.693 0.217,1.675 0.21,1.65 0.21,1.65 0.21,0.925 0.206,0.906 0.195,0.89 0.179,0.879 0.16,0.875 0.16,0.875 -0.16,0.875 -0.179,0.879 -0.195,0.89 -0.206,0.906 -0.21,0.925 -0.21,0.925 -0.21,1.65 -0.214,1.669 -0.225,1.685 -0.241,1.696 -0.26,1.7 -0.26,1.7 -0.39,1.7 -0.415,1.693 -0.433,1.675 -0.44,1.65 -0.44,1.65 -0.44,0.925 -0.444,0.906 -0.455,0.89 -0.471,0.879 -0.49,0.875 -0.49,0.875 -0.7,0.875 -0.719,0.871 -0.735,0.86 -0.746,0.844 -0.75,0.825 -0.75,0.825
  silkscreen extent -2.38,-1.55 1.55,1.55, body extent -1.5,-1.5 1.5,1.5, height 1
DRY0006A [mm] "USON-6"
  rrect67% 0.45x0.3 smd paste-0.05 mask-0.05: 1(-0.275,0.5)
  rrect67% 0.4x0.3 smd paste-0.05 mask-0.05: 2(-0.3,0) 3(-0.3,-0.5) 4(0.3,-0.5) 5(0.3,0) 6(0.3,0.5)
  body extent 0,0 0,0
DW0016B-MFG [mm]
  rrect17% 1.65x0.6 smd paste+0 mask+0: 1(-4.875,4.445) 2(-4.875,3.175) 3(-4.875,1.905) 4(-4.875,0.635) 5(-4.875,-0.635) 6(-4.875,-1.905) 7(-4.875,-3.175) 8(-4.875,-4.445) 9(4.875,-4.445) 10(4.875,-3.175) 11(4.875,-1.905) 12(4.875,-0.635) 13(4.875,0.635) 14(4.875,1.905) 15(4.875,3.175) 16(4.875,4.445)
  silkscreen extent -6.37,-5.25 3.5,5.25, body extent -5.8,-5.5 5.8,5.5, height 0.25
FCC_disclaimer [mil]
Fiducial10-20 [mm]
  round 1 smd mask+0.5: 1(0,0)
  Top Signal keep-out circle w1.178: c0,0 r0.5
FP-830064296_SMT4_3MM4_2MM7-MFG [mm]
  rrect9% 1.4x1.15 smd paste+0 mask+0: 1(-1.1,-0.8) 2(1.1,-0.8) 3(1.1,0.8) 4(-1.1,0.8)
  silkscreen extent -2.17,-2.05 2.17,1.35, body extent -1.9,-1.48 1.9,1.48, height 0.25
FP-61300421121_HDR4-MFG [mm]
  rrect6% 1.7x1.7 hole 1.1 paste-1000 mask+0: 1(-1.27,1.27)
  round 1.7 hole 1.1 paste-1000 mask+0: 2(-1.27,-1.27) 3(1.27,1.27) 4(1.27,-1.27)
  silkscreen extent -2.69,-2.62 2.69,3.22, body extent -2.54,-2.54 2.54,2.54, height 5.54
FP-61301221121_HDR12-MFG [mm]
  rrect6% 1.7x1.7 hole 1.1 paste-1000 mask+0: 1(-6.35,-1.27)
  round 1.7 hole 1.1 paste-1000 mask+0: 2(-6.35,1.27) 3(-3.81,-1.27) 4(-3.81,1.27) 5(-1.27,-1.27) 6(-1.27,1.27) 7(1.27,-1.27) 8(1.27,1.27) 9(3.81,-1.27) 10(3.81,1.27) 11(6.35,-1.27) 12(6.35,1.27)
  silkscreen extent -7.77,-3.22 7.77,2.62, body extent -7.87,-2.72 7.87,2.72, height 0.25
FP-74479773210_0805-MFG [mm] "Recommended Land Pattern"
  rrect13% 0.8x1.4 smd paste+0 mask+0: 1(-0.9,0) 2(0.9,0)
  silkscreen extent -0.13,-0.72 0.13,0.72, body extent -1,-0.63 1,0.63, height 0.6
FP-830108207209_SMT_CRYSTAL_3MM2_2MM5-MFG [mm]
  rrect9% 1.4x1.15 smd paste+0 mask+0: 1(-1.1,-0.8) 2(1.1,-0.8) 3(1.1,0.8) 4(-1.1,0.8)
  silkscreen extent -1.22,-2.05 0,1.35, body extent -1.9,-1.48 1.9,1.47, height 0.25
FP-885012106011_0603-MFG [mm] "Recommended Land Pattern"
  rrect13% 0.8x0.8 smd paste+0 mask+0: 1(-0.75,0) 2(0.75,0)
  silkscreen extent -0.85,-0.77 0.85,0.77, body extent -0.8,-0.4 0.8,0.4, height 0.87
FP-885012106031_0603-MFG [mm] "Recommended Land Pattern"
  rrect13% 0.8x0.8 smd paste+0 mask+0: 1(-0.75,0) 2(0.75,0)
  silkscreen extent -0.9,-0.77 0.9,0.77, body extent -1.25,-0.6 1.25,0.6, height 0.25
FP-885012205018_0402-MFG [mm]
  rrect20% 0.5x0.5 smd paste+0 mask+0: 1(-0.5,0) 2(0.5,0)
  silkscreen extent -0.5,-0.63 0.5,0.63, body extent -0.5,-0.25 0.5,0.25, height 0.55
FP-885012205050_0402-MFG [mm]
  rrect20% 0.5x0.5 smd paste+0 mask+0: 1(-0.5,0) 2(0.5,0)
  silkscreen extent -0.53,-0.63 0.53,0.63, body extent -0.85,-0.38 0.85,0.38, height 0.25
FP-885012205064_0402-MFG [mm]
  rrect20% 0.5x0.5 smd paste+0 mask+0: 1(-0.5,0) 2(0.5,0)
  silkscreen extent -0.53,-0.63 0.53,0.63, body extent -0.85,-0.38 0.85,0.38, height 0.25
FP-885012206040_0603-MFG [mm] "Recommended Land Pattern"
  rrect13% 0.8x0.8 smd paste+0 mask+0: 1(-0.75,0) 2(0.75,0)
  silkscreen extent -0.85,-0.77 0.85,0.77, body extent -0.8,-0.4 0.8,0.4, height 0.87
FP-885392005127_0402-MFG [mm] "Recommended Land Pattern"
  rrect20% 0.5x0.5 smd paste+0 mask+0: 1(-0.5,0) 2(0.5,0)
  silkscreen extent -0.5,-0.63 0.5,0.63, body extent -0.85,-0.37 0.85,0.37, height 0.25
FP-MUP-U22001_CONN_USB_8MM94_8MM0-MFG [mm]
  rrect100% 0.6x1.9 hole 1.9 slot 0.6 at 0 deg paste-1000 mask+0: 1(-4.32,3.35) 2(4.32,3.35)
  round 1.207 smd paste-1000 mask+0: 1(-4.25,2.92) 2(4.25,2.92)
  round 1.207 smd far side paste-1000 mask+0: 1(-4.25,2.92) 2(4.25,2.92)
  rrect100% 1.25x0.7 hole 0.7 slot 1.25 at 0 deg paste-1000 mask+0: 1(-3.995,2.75) 2(3.995,2.75)
  rrect100% 0.7x1.5 hole 1.5 slot 0.7 at 0 deg paste-1000 mask+0: 3(-5.85,-1.95) 4(5.85,-1.95)
  round 1.17 smd far side paste-1000 mask+0: 3(-5.85,-1.625) 4(5.85,-1.625)
  round 1.17 smd paste-1000 mask+0: 3(-5.85,-1.625) 4(5.85,-1.625)
  rrect37% 0.27x0.9 smd paste+0 mask+0.051: A1(-2.625,4.05) A2(-2.125,4.05) A3(-1.625,4.05) A4(-1.125,4.05) A5(-0.625,4.05) A6(-0.125,4.05) A7(0.375,4.05) A8(0.875,4.05) A9(1.375,4.05) A10(1.875,4.05) A11(2.375,4.05) A12(2.875,4.05)
  rrect37% 0.27x0.8 smd paste+0 mask+0.051: B1(2.625,2.45) B2(2.125,2.45) B3(1.625,2.45) B4(1.125,2.45) B5(0.625,2.45) B6(0.125,2.45) B7(-0.375,2.45) B8(-0.875,2.45) B9(-1.375,2.45) B10(-1.875,2.45) B11(-2.375,2.45) B12(-2.875,2.45)
  Top Signal region: 3.72,3.35 3.72,4.05 3.72,4.169 3.811,4.39 3.98,4.559 4.201,4.65 4.32,4.65 4.439,4.65 4.66,4.559 4.829,4.39 4.92,4.169 4.92,4.05 4.92,4.05 4.92,2.85 4.92,2.731 4.829,2.51 4.66,2.341 4.439,2.25 4.32,2.25 4.32,2.25 3.82,2.25 3.711,2.25 3.508,2.334 3.354,2.488 3.27,2.691 3.27,2.8 3.268,2.898 3.332,3.082 3.456,3.233 3.624,3.332 3.72,3.35 3.72,3.35
  Top Signal region: 6.5,-2.349 6.5,-2.472 6.411,-2.701 6.244,-2.882 6.023,-2.99 5.9,-2.999 5.833,-3.004 5.699,-2.987 5.572,-2.942 5.457,-2.873 5.358,-2.781 5.281,-2.672 5.227,-2.548 5.2,-2.416 5.2,-2.349 5.2,-2.349 5.2,-0.749 5.2,-0.65 5.276,-0.466 5.417,-0.325 5.601,-0.249 5.7,-0.249 5.7,-0.249 6,-0.249 6.099,-0.249 6.283,-0.325 6.424,-0.466 6.5,-0.65 6.5,-0.749 6.5,-0.749
  Top Signal region: -6.5,-2.349 -6.5,-2.472 -6.411,-2.701 -6.244,-2.882 -6.023,-2.99 -5.9,-2.999 -5.9,-2.999 -5.833,-3.004 -5.699,-2.987 -5.572,-2.942 -5.457,-2.873 -5.358,-2.781 -5.281,-2.672 -5.227,-2.548 -5.2,-2.416 -5.2,-2.349 -5.2,-2.349 -5.2,-0.749 -5.2,-0.65 -5.276,-0.466 -5.417,-0.325 -5.601,-0.249 -5.7,-0.249 -5.7,-0.249 -6,-0.249 -6.099,-0.249 -6.283,-0.325 -6.424,-0.466 -6.5,-0.65 -6.5,-0.749 -6.5,-0.749
  Top Signal region: -3.72,3.35 -3.72,4.05 -3.72,4.169 -3.811,4.39 -3.98,4.559 -4.201,4.65 -4.32,4.65 -4.439,4.65 -4.66,4.559 -4.829,4.39 -4.92,4.169 -4.92,4.05 -4.92,4.05 -4.92,2.85 -4.92,2.731 -4.829,2.51 -4.66,2.341 -4.439,2.25 -4.32,2.25 -4.32,2.25 -3.82,2.25 -3.711,2.25 -3.508,2.334 -3.354,2.488 -3.27,2.691 -3.27,2.8 -3.268,2.898 -3.332,3.082 -3.456,3.233 -3.624,3.332 -3.72,3.35
  Bottom Signal region: 3.72,3.35 3.72,4.05 3.72,4.169 3.811,4.39 3.98,4.559 4.201,4.65 4.32,4.65 4.439,4.65 4.66,4.559 4.829,4.39 4.92,4.169 4.92,4.05 4.92,4.05 4.92,2.85 4.92,2.731 4.829,2.51 4.66,2.341 4.439,2.25 4.32,2.25 4.32,2.25 3.82,2.25 3.711,2.25 3.508,2.334 3.354,2.488 3.27,2.691 3.27,2.8 3.268,2.898 3.332,3.082 3.456,3.233 3.624,3.332 3.72,3.35
  Bottom Signal region: -3.72,3.35 -3.72,4.05 -3.72,4.169 -3.811,4.39 -3.98,4.559 -4.201,4.65 -4.32,4.65 -4.439,4.65 -4.66,4.559 -4.829,4.39 -4.92,4.169 -4.92,4.05 -4.92,4.05 -4.92,2.85 -4.92,2.731 -4.829,2.51 -4.66,2.341 -4.439,2.25 -4.32,2.25 -4.32,2.25 -3.82,2.25 -3.711,2.25 -3.508,2.334 -3.354,2.488 -3.27,2.691 -3.27,2.8 -3.268,2.898 -3.332,3.082 -3.456,3.233 -3.624,3.332 -3.72,3.35
  Bottom Signal region: 6.5,-2.349 6.5,-2.472 6.411,-2.701 6.244,-2.882 6.023,-2.99 5.9,-2.999 5.833,-3.004 5.699,-2.987 5.572,-2.942 5.457,-2.873 5.358,-2.781 5.281,-2.672 5.227,-2.548 5.2,-2.416 5.2,-2.349 5.2,-2.349 5.2,-0.749 5.2,-0.65 5.276,-0.466 5.417,-0.325 5.601,-0.249 5.7,-0.249 5.7,-0.249 6,-0.249 6.099,-0.249 6.283,-0.325 6.424,-0.466 6.5,-0.65 6.5,-0.749 6.5,-0.749
  Bottom Signal region: -6.5,-2.349 -6.5,-2.472 -6.411,-2.701 -6.244,-2.882 -6.023,-2.99 -5.9,-2.999 -5.833,-3.004 -5.699,-2.987 -5.572,-2.942 -5.457,-2.873 -5.358,-2.781 -5.281,-2.672 -5.227,-2.548 -5.2,-2.416 -5.2,-2.349 -5.2,-2.349 -5.2,-0.749 -5.2,-0.65 -5.276,-0.466 -5.417,-0.325 -5.601,-0.249 -5.7,-0.249 -5.7,-0.249 -6,-0.249 -6.099,-0.249 -6.283,-0.325 -6.424,-0.466 -6.5,-0.65 -6.5,-0.749 -6.5,-0.749
  Keep-Out Layer lines w0.2: 4.7,-3.5 4.7,0.75 ccw(c4.7,1.25) 5.2,1.25 ccw(c4.7,1.25) 4.7,1.75 -4.7,1.75 ccw(c-4.7,1.25) -5.2,1.25 ccw(c-4.7,1.25) -4.7,0.75 -4.7,-3.5
  silkscreen extent -6,0.13 6,5.17, body extent -6.6,-4.23 6.6,4.75, height 0.25
KY_MAE-10 [mm] "Spacer Nylon Support"
  round 2.8 hole 3 unplated mask+0.102: ""(0,0)
  body extent -3.19,-2.75 3.19,2.75, height 10
NPTH125mil [mil]
  round 120 hole 125 unplated mask+15: 1(0,0)
PDT0128A [mm] "Thin QFP, 128-Leads, Body 14x14mm, Pitch 0.4mm"
  oval 1.4x0.2 smd: 1(-7.7,6.2) 2(-7.7,5.8) 3(-7.7,5.4) 4(-7.7,5) 5(-7.7,4.6) 6(-7.7,4.2) 7(-7.7,3.8) 8(-7.7,3.4) 9(-7.7,3) 10(-7.7,2.6) 11(-7.7,2.2) 12(-7.7,1.8) 13(-7.7,1.4) 14(-7.7,1) 15(-7.7,0.6) 16(-7.7,0.2) 17(-7.7,-0.2) 18(-7.7,-0.6) 19(-7.7,-1) 20(-7.7,-1.4) 21(-7.7,-1.8) 22(-7.7,-2.2) 23(-7.7,-2.6) 24(-7.7,-3) 25(-7.7,-3.4) 26(-7.7,-3.8) 27(-7.7,-4.2) 28(-7.7,-4.6) 29(-7.7,-5) 30(-7.7,-5.4) 31(-7.7,-5.8) 32(-7.7,-6.2) 65(7.7,-6.2) 66(7.7,-5.8) 67(7.7,-5.4) 68(7.7,-5) 69(7.7,-4.6) 70(7.7,-4.2) 71(7.7,-3.8) 72(7.7,-3.4) 73(7.7,-3) 74(7.7,-2.6) 75(7.7,-2.2) 76(7.7,-1.8) 77(7.7,-1.4) 78(7.7,-1) 79(7.7,-0.6) 80(7.7,-0.2) 81(7.7,0.2) 82(7.7,0.6) 83(7.7,1) 84(7.7,1.4) 85(7.7,1.8) 86(7.7,2.2) 87(7.7,2.6) 88(7.7,3) 89(7.7,3.4) 90(7.7,3.8) 91(7.7,4.2) 92(7.7,4.6) 93(7.7,5) 94(7.7,5.4) 95(7.7,5.8) 96(7.7,6.2)
  oval 0.2x1.4 smd: 33(-6.2,-7.7) 34(-5.8,-7.7) 35(-5.4,-7.7) 36(-5,-7.7) 37(-4.6,-7.7) 38(-4.2,-7.7) 39(-3.8,-7.7) 40(-3.4,-7.7) 41(-3,-7.7) 42(-2.6,-7.7) 43(-2.2,-7.7) 44(-1.8,-7.7) 45(-1.4,-7.7) 46(-1,-7.7) 47(-0.6,-7.7) 48(-0.2,-7.7) 49(0.2,-7.7) 50(0.6,-7.7) 51(1,-7.7) 52(1.4,-7.7) 53(1.8,-7.7) 54(2.2,-7.7) 55(2.6,-7.7) 56(3,-7.7) 57(3.4,-7.7) 58(3.8,-7.7) 59(4.2,-7.7) 60(4.6,-7.7) 61(5,-7.7) 62(5.4,-7.7) 63(5.8,-7.7) 64(6.2,-7.7) 97(6.2,7.7) 98(5.8,7.7) 99(5.4,7.7) 100(5,7.7) 101(4.6,7.7) 102(4.2,7.7) 103(3.8,7.7) 104(3.4,7.7) 105(3,7.7) 106(2.6,7.7) 107(2.2,7.7) 108(1.8,7.7) 109(1.4,7.7) 110(1,7.7) 111(0.6,7.7) 112(0.2,7.7) 113(-0.2,7.7) 114(-0.6,7.7) 115(-1,7.7) 116(-1.4,7.7) 117(-1.8,7.7) 118(-2.2,7.7) 119(-2.6,7.7) 120(-3,7.7) 121(-3.4,7.7) 122(-3.8,7.7) 123(-4.2,7.7) 124(-4.6,7.7) 125(-5,7.7) 126(-5.4,7.7) 127(-5.8,7.7) 128(-6.2,7.7)
  silkscreen extent -7.7,-6.3 6.3,6.99, body extent -8,-8 8,8, height 1.07
PT0048A-MFG [mm] "Recommended Land Pattern"
  rrect33% 1.6x0.3 smd paste+0 mask+0: 1(-4.1,2.75) 2(-4.1,2.25) 3(-4.1,1.75) 4(-4.1,1.25) 5(-4.1,0.75) 6(-4.1,0.25) 7(-4.1,-0.25) 8(-4.1,-0.75) 9(-4.1,-1.25) 10(-4.1,-1.75) 11(-4.1,-2.25) 12(-4.1,-2.75) 25(4.1,-2.75) 26(4.1,-2.25) 27(4.1,-1.75) 28(4.1,-1.25) 29(4.1,-0.75) 30(4.1,-0.25) 31(4.1,0.25) 32(4.1,0.75) 33(4.1,1.25) 34(4.1,1.75) 35(4.1,2.25) 36(4.1,2.75)
  rrect33% 0.3x1.6 smd paste+0 mask+0: 13(-2.75,-4.1) 14(-2.25,-4.1) 15(-1.75,-4.1) 16(-1.25,-4.1) 17(-0.75,-4.1) 18(-0.25,-4.1) 19(0.25,-4.1) 20(0.75,-4.1) 21(1.25,-4.1) 22(1.75,-4.1) 23(2.25,-4.1) 24(2.75,-4.1) 37(2.75,4.1) 38(2.25,4.1) 39(1.75,4.1) 40(1.25,4.1) 41(0.75,4.1) 42(0.25,4.1) 43(-0.25,4.1) 44(-0.75,4.1) 45(-1.25,4.1) 46(-1.75,4.1) 47(-2.25,4.1) 48(-2.75,4.1)
  silkscreen extent -4.22,-2.75 2.75,3.57, body extent -4.5,-4.5 4.5,4.5, height 1.6
PW0016A-MFG [mm]
  rrect22% 1.5x0.45 smd paste+0 mask+0: 1(-2.9,2.275) 2(-2.9,1.625) 3(-2.9,0.975) 4(-2.9,0.325) 5(-2.9,-0.325) 6(-2.9,-0.975) 7(-2.9,-1.625) 8(-2.9,-2.275) 9(2.9,-2.275) 10(2.9,-1.625) 11(2.9,-0.975) 12(2.9,-0.325) 13(2.9,0.325) 14(2.9,0.975) 15(2.9,1.625) 16(2.9,2.275)
  silkscreen extent -4.37,-2.55 1.78,2.55, body extent -3.2,-2.5 3.2,2.5, height 1.2
PW0024A_N [mm] "TSOP, 24-Leads, Body 7.8x4.4mm, Pitch 0.65mm, IPC Medium Density"
  oval 1.4x0.45 smd: 1(-2.95,3.575) 2(-2.95,2.925) 3(-2.95,2.275) 4(-2.95,1.625) 5(-2.95,0.975) 6(-2.95,0.325) 7(-2.95,-0.325) 8(-2.95,-0.975) 9(-2.95,-1.625) 10(-2.95,-2.275) 11(-2.95,-2.925) 12(-2.95,-3.575) 13(2.95,-3.575) 14(2.95,-2.925) 15(2.95,-2.275) 16(2.95,-1.625) 17(2.95,-0.975) 18(2.95,-0.325) 19(2.95,0.325) 20(2.95,0.975) 21(2.95,1.625) 22(2.95,2.275) 23(2.95,2.925) 24(2.95,3.575)
  silkscreen extent -3.51,-3.95 1.6,4.04, body extent 0,0 0,0, height 0.62
Samtec_TSM-102-01-x-DV [mil] "Header, 2.54mm, 2x2, SMT"
  rect 120x50 smd: 1(-97.44,-50) 2(97.44,-50) 3(-97.44,50) 4(97.44,50)
  silkscreen extent -69,-104 65,100, body extent -151,-100 152,100, height 380
SW_1188E [mm] "SMD, 4-Leads, Body 7.8x3.5mm"
  rrect10% 1x1.45 smd: 1(-1.1,3.375) 2(-1.1,-3.375)
  rrect11% 1.3x0.9 smd: 3(0.7,2.1) 4(0.7,-2.1)
  round 0 hole 0.9 unplated mask+0.051: ""(-0.35,1.15) ""(-0.35,-1.15)
  silkscreen extent -1.98,-2.28 0.95,2.28, body extent -2.55,-3.9 1.05,3.9, height 3.5
SW_CAS-120TA [mm] "COPAL ELECTRONICS"
  rect 1.6x1 smd: 1(-1.15,1.75) 2(1.15,0) 3(-1.15,-1.75)
  silkscreen extent -2,-2.85 1.4,2.92, body extent -1.4,-2.85 1.4,2.85, height 2.51
SW_CAS-D20TA [mm] "SMD, 6-Leads, Body 5.4x3.9mm, Pitch 1.75mm"
  rect 1.6x1 smd: 1(-1.85,1.75) 2(-1.85,0) 3(-1.85,-1.75) 4(1.85,1.75) 5(1.85,0) 6(1.85,-1.75)
  silkscreen extent -1.95,-2.7 1.95,2.9, body extent -2.1,-2.7 2.1,2.7, height 2.5
TI_Stacked_Overlay_Medium [mil]
  silkscreen extent -576,-136 576,135
TI_Symbol_Overlay_Small [mil]
  silkscreen extent -90,-88 91,88
TP_50MIL-25MILHOLE [mil]
  round 50 hole 25: 1(0,0)
WEEE_Minimum [mil] "WEEElie bin"
  silkscreen extent -95,-172 99,104
WL-SMCW_Blue_0805 [mm] "SMD, 2-Leads, Body 2x1.25mm"
  rect 1.1x1.2 smd: 1(-1.05,0) 2(1.05,0)
  silkscreen extent -2.4,-1.1 1.5,1.1, body extent -1,-0.62 1,0.63, height 0.7
WL-SMCW_Green_0805 [mm] "SMD, 2-Leads, Body 2x1.25mm"
  rect 1.1x1.2 smd: 1(-1.05,0) 2(1.05,0)
  silkscreen extent -2.4,-1.1 1.5,1.1, body extent -1,-0.62 1,0.63, height 0.7
WL-SMCW_RED_0805 [mm] "SMD, 2-Leads, Body 1.6x0.8mm"
  rect 1.1x1.2 smd: 1(-1.05,0) 2(1.05,0)
  silkscreen extent -2.4,-1.1 1.5,1.1, body extent -1,-0.62 1,0.63, height 0.7
Wurth_60900213421 [mil] "Shunt, 2.54mm, Black"
  round 1 on Mech3: 0(0,0)
  body extent -105,-57 91,39, height 338
WURTH_61300211121#1 [mm] "Header, 2.54mm, 2x1, TH"
  rect 1.65x1.65 hole 1.15: 1(-1.27,0)
  round 1.65 hole 1.15: 2(1.27,0)
  silkscreen extent -2.54,-1.27 2.54,1.6, body extent -2.54,-1.27 2.54,1.27, height 8.54
WURTH_61300211121#2 [mm] "Header, 2.54mm, 2x1, TH"
  rrect50% 1.65x1.65 hole 1.15: 1(-1.27,0)
  round 1.65 hole 1.15: 2(1.27,0)
  body extent -2.54,-1.27 2.54,1.27, height 8.54
WURTH_61300311121 [mm] "Header, 2.54mm, 3x1, TH"
  rect 1.65x1.65 hole 1.15: 1(-2.54,0)
  round 1.65 hole 1.15: 2(0,0) 3(2.54,0)
  silkscreen extent -3.81,-1.27 3.81,1.6, body extent -3.81,-1.27 3.81,1.27, height 8.54
Wurth_61300511121 [mm] "Header, 2.54mm, 5x1, TH"
  rrect50% 1.65x1.65 hole 1.1: 1(-5.08,0)
  round 1.65 hole 1.1: 2(-2.54,0) 3(0,0) 4(2.54,0) 5(5.08,0)
  body extent -6.35,-1.27 6.35,1.27, height 8.54
YFF0006AEAE [mm] "DSBGA-6"
  round 0.23 smd paste-0.13 mask+0.038: A1(-0.2,0.4) A2(0.2,0.4) B1(-0.2,0) B2(0.2,0) C1(-0.2,-0.4) C2(0.2,-0.4)
  body extent -0.45,-0.65 0.45,0.65, height 0.63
